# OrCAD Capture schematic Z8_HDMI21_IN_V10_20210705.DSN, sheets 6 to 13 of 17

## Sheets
6 PAGE08-HDMI20 OUT2: size Custom
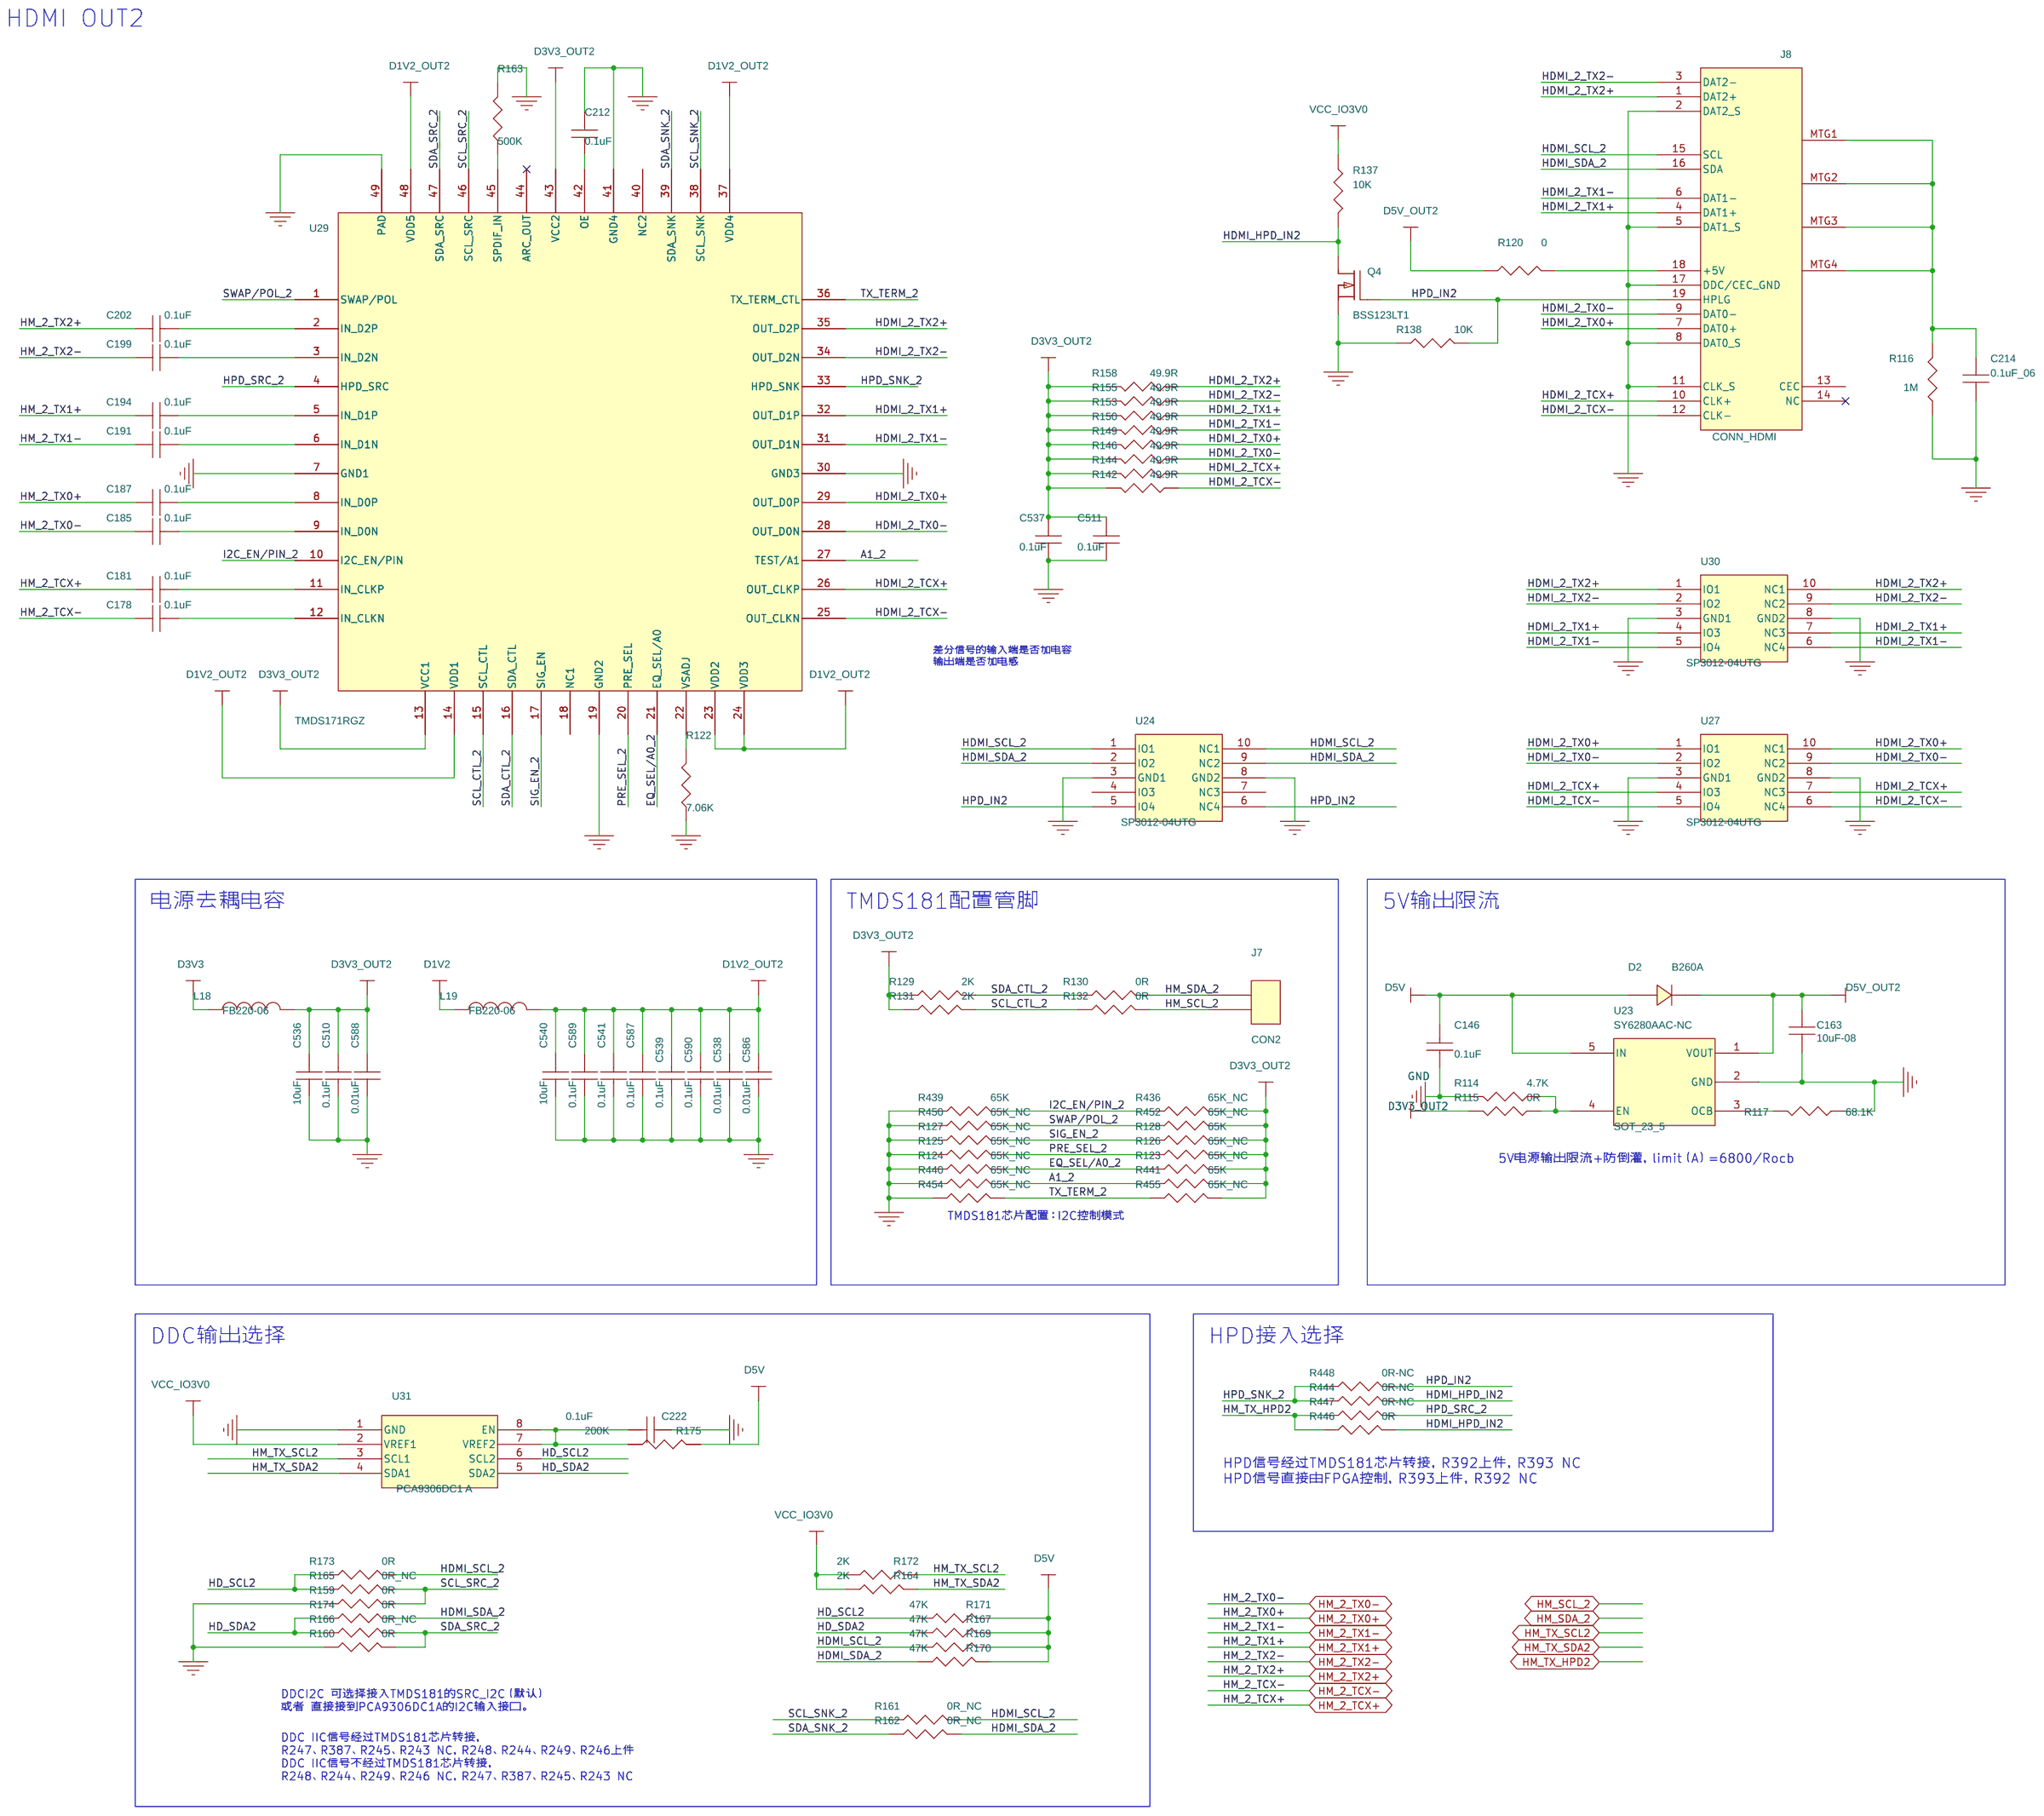
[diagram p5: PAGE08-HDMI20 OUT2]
7 PAGE07-HDMI20 OUT1: size Custom
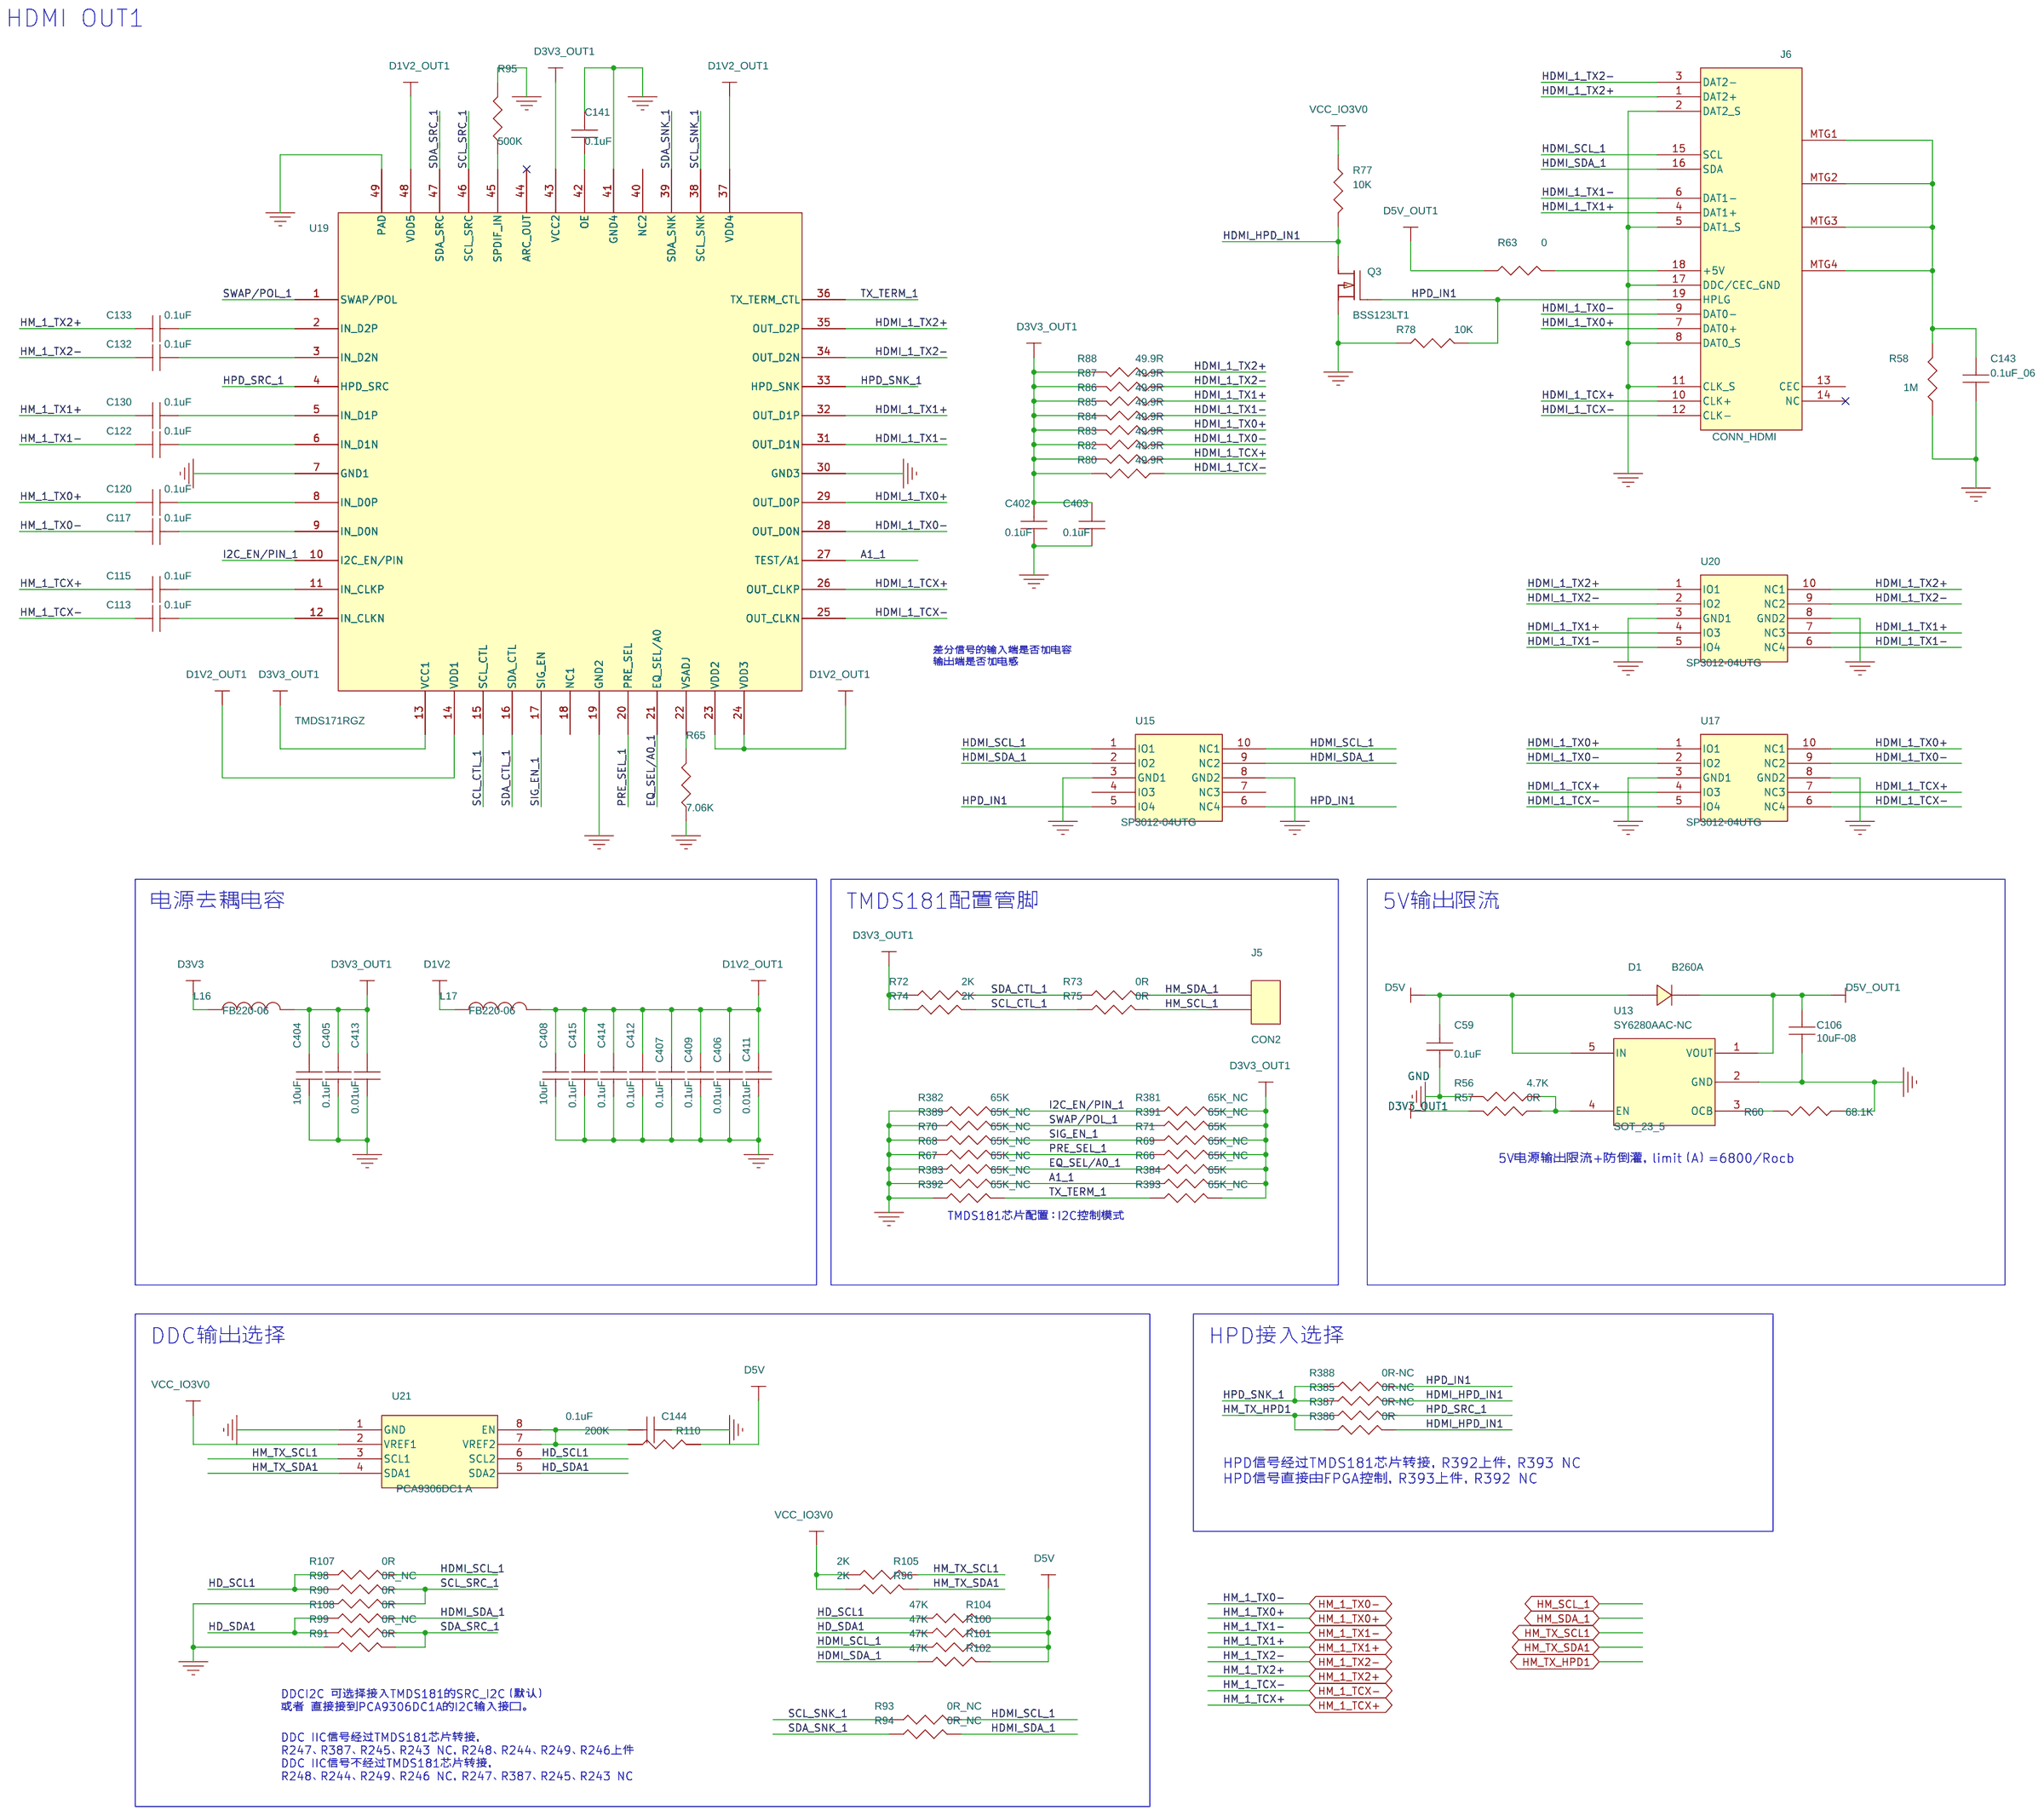
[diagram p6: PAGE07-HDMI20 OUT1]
8 PAGE05-STM32F030: size B
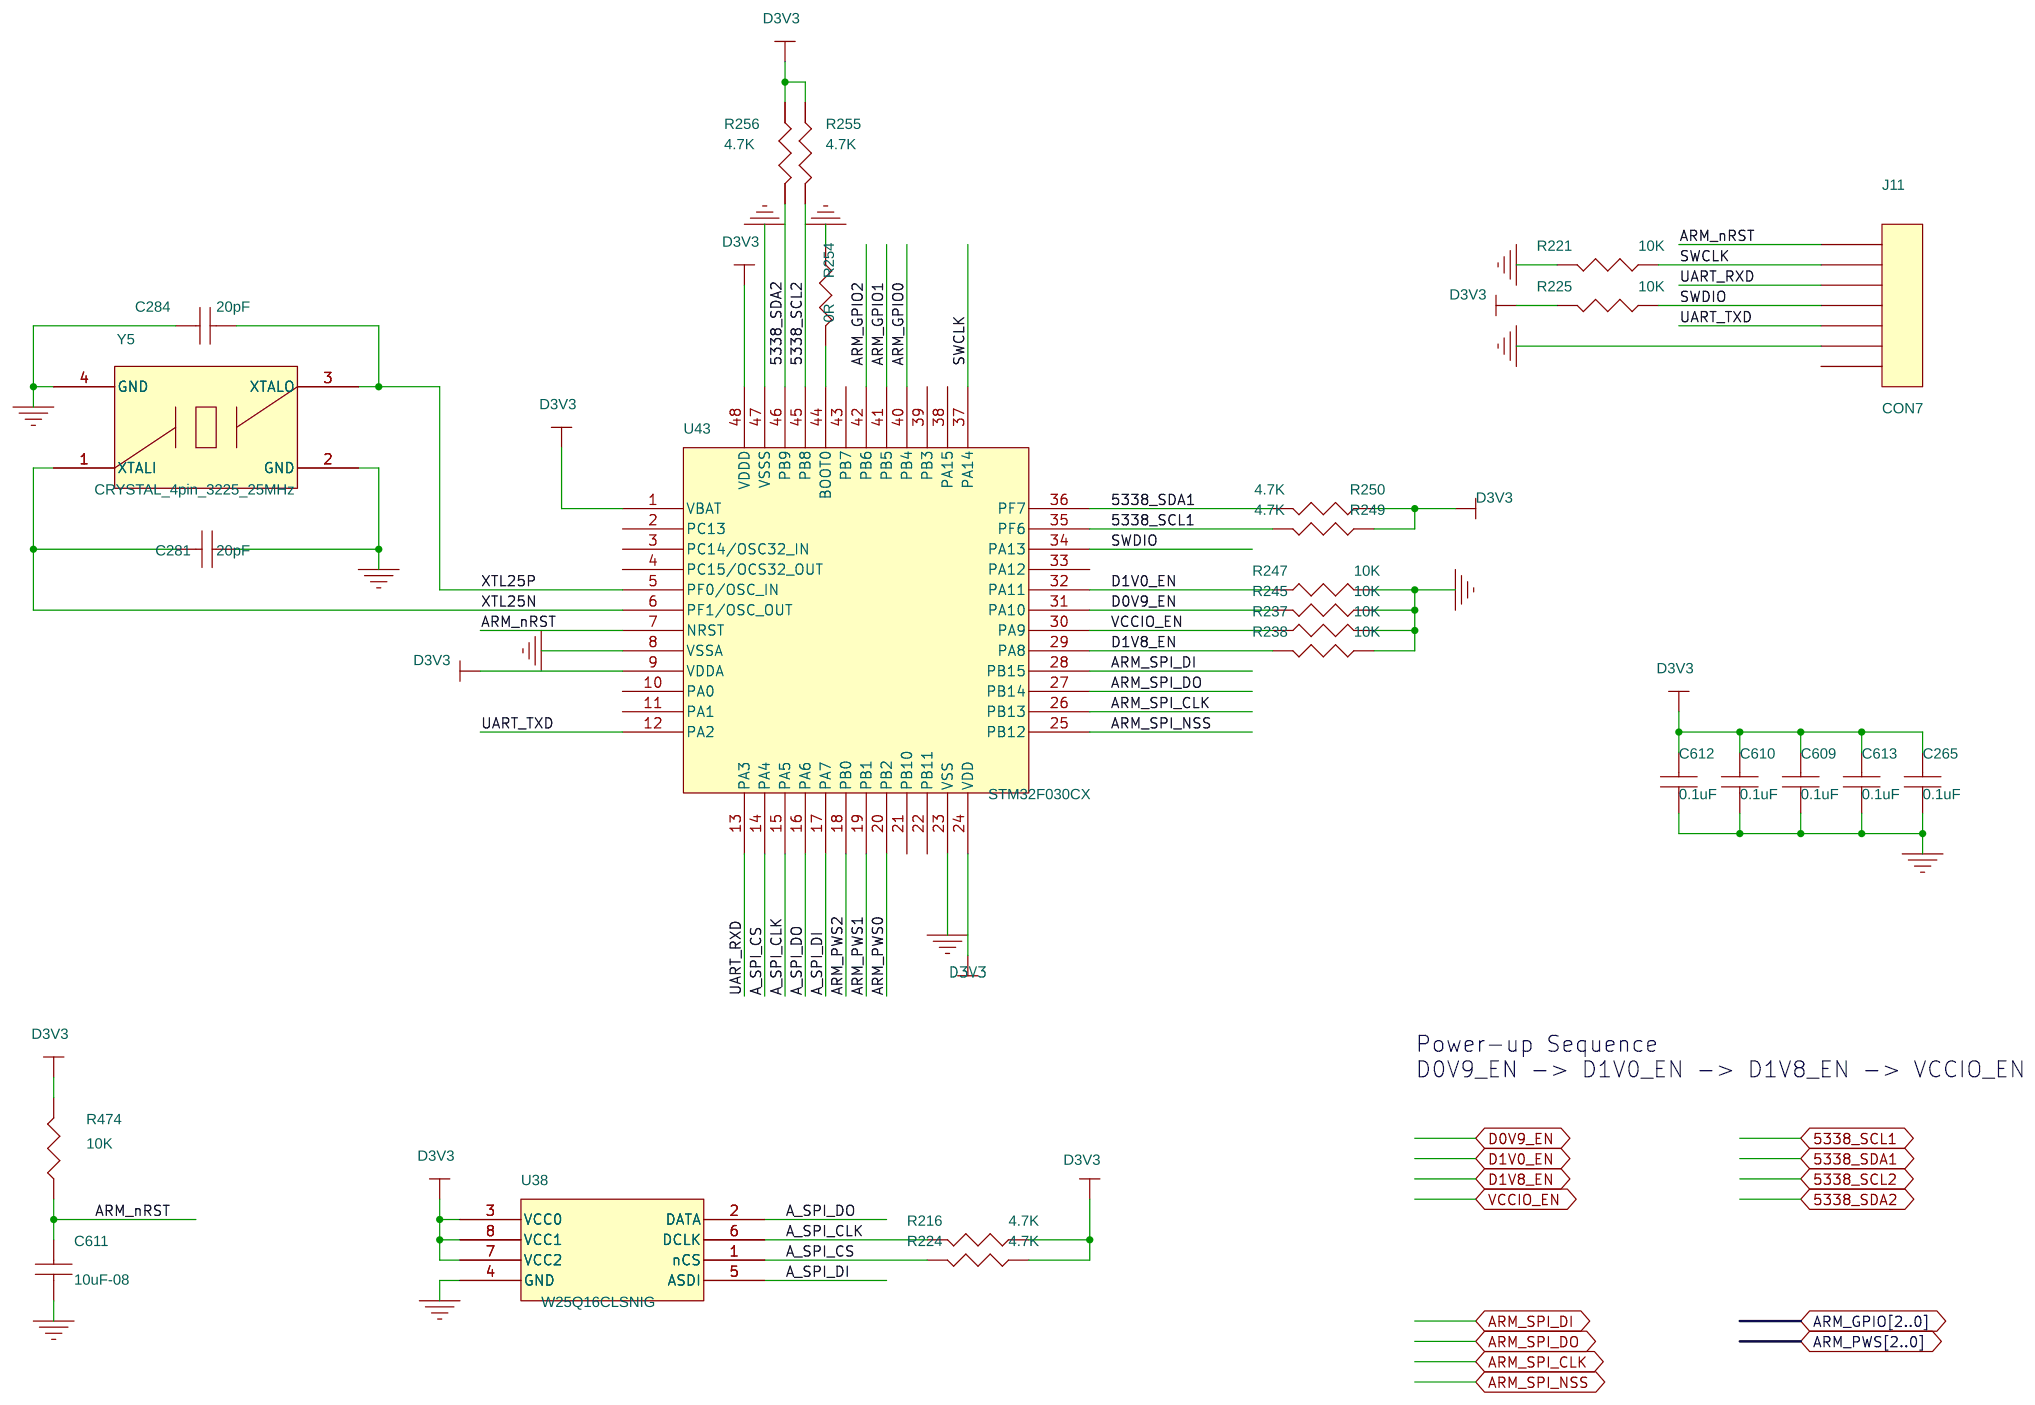
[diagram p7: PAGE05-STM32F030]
9 PAGE01-Description
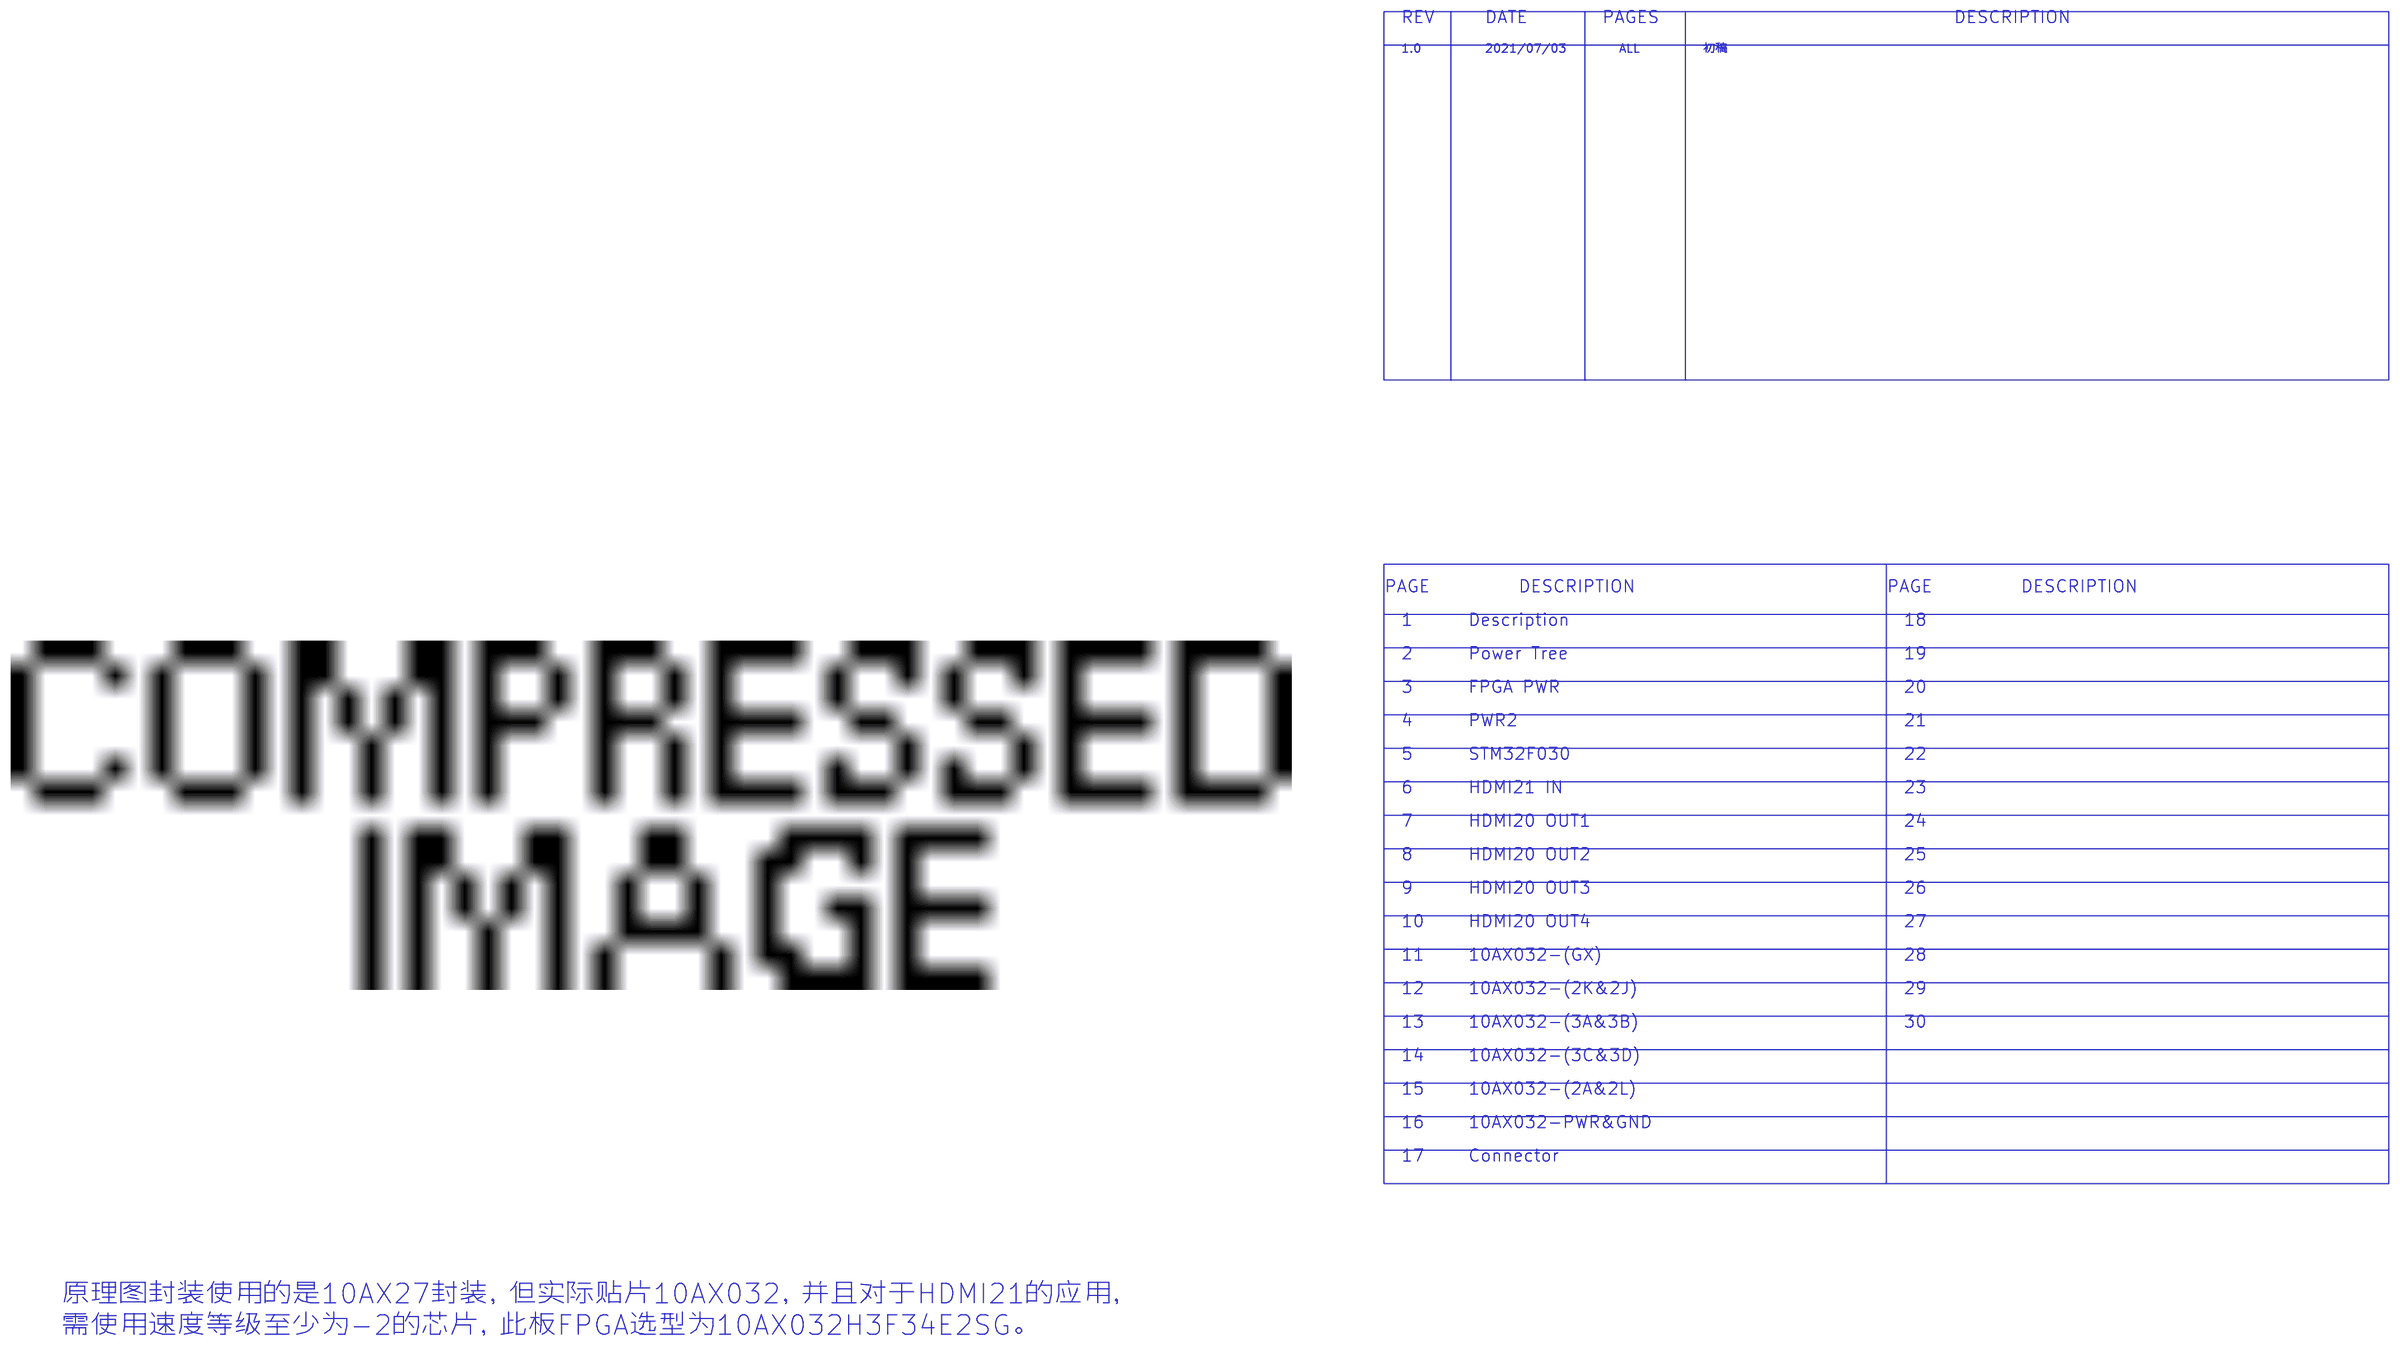
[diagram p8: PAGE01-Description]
10 PAGE04-PWR2: size Custom
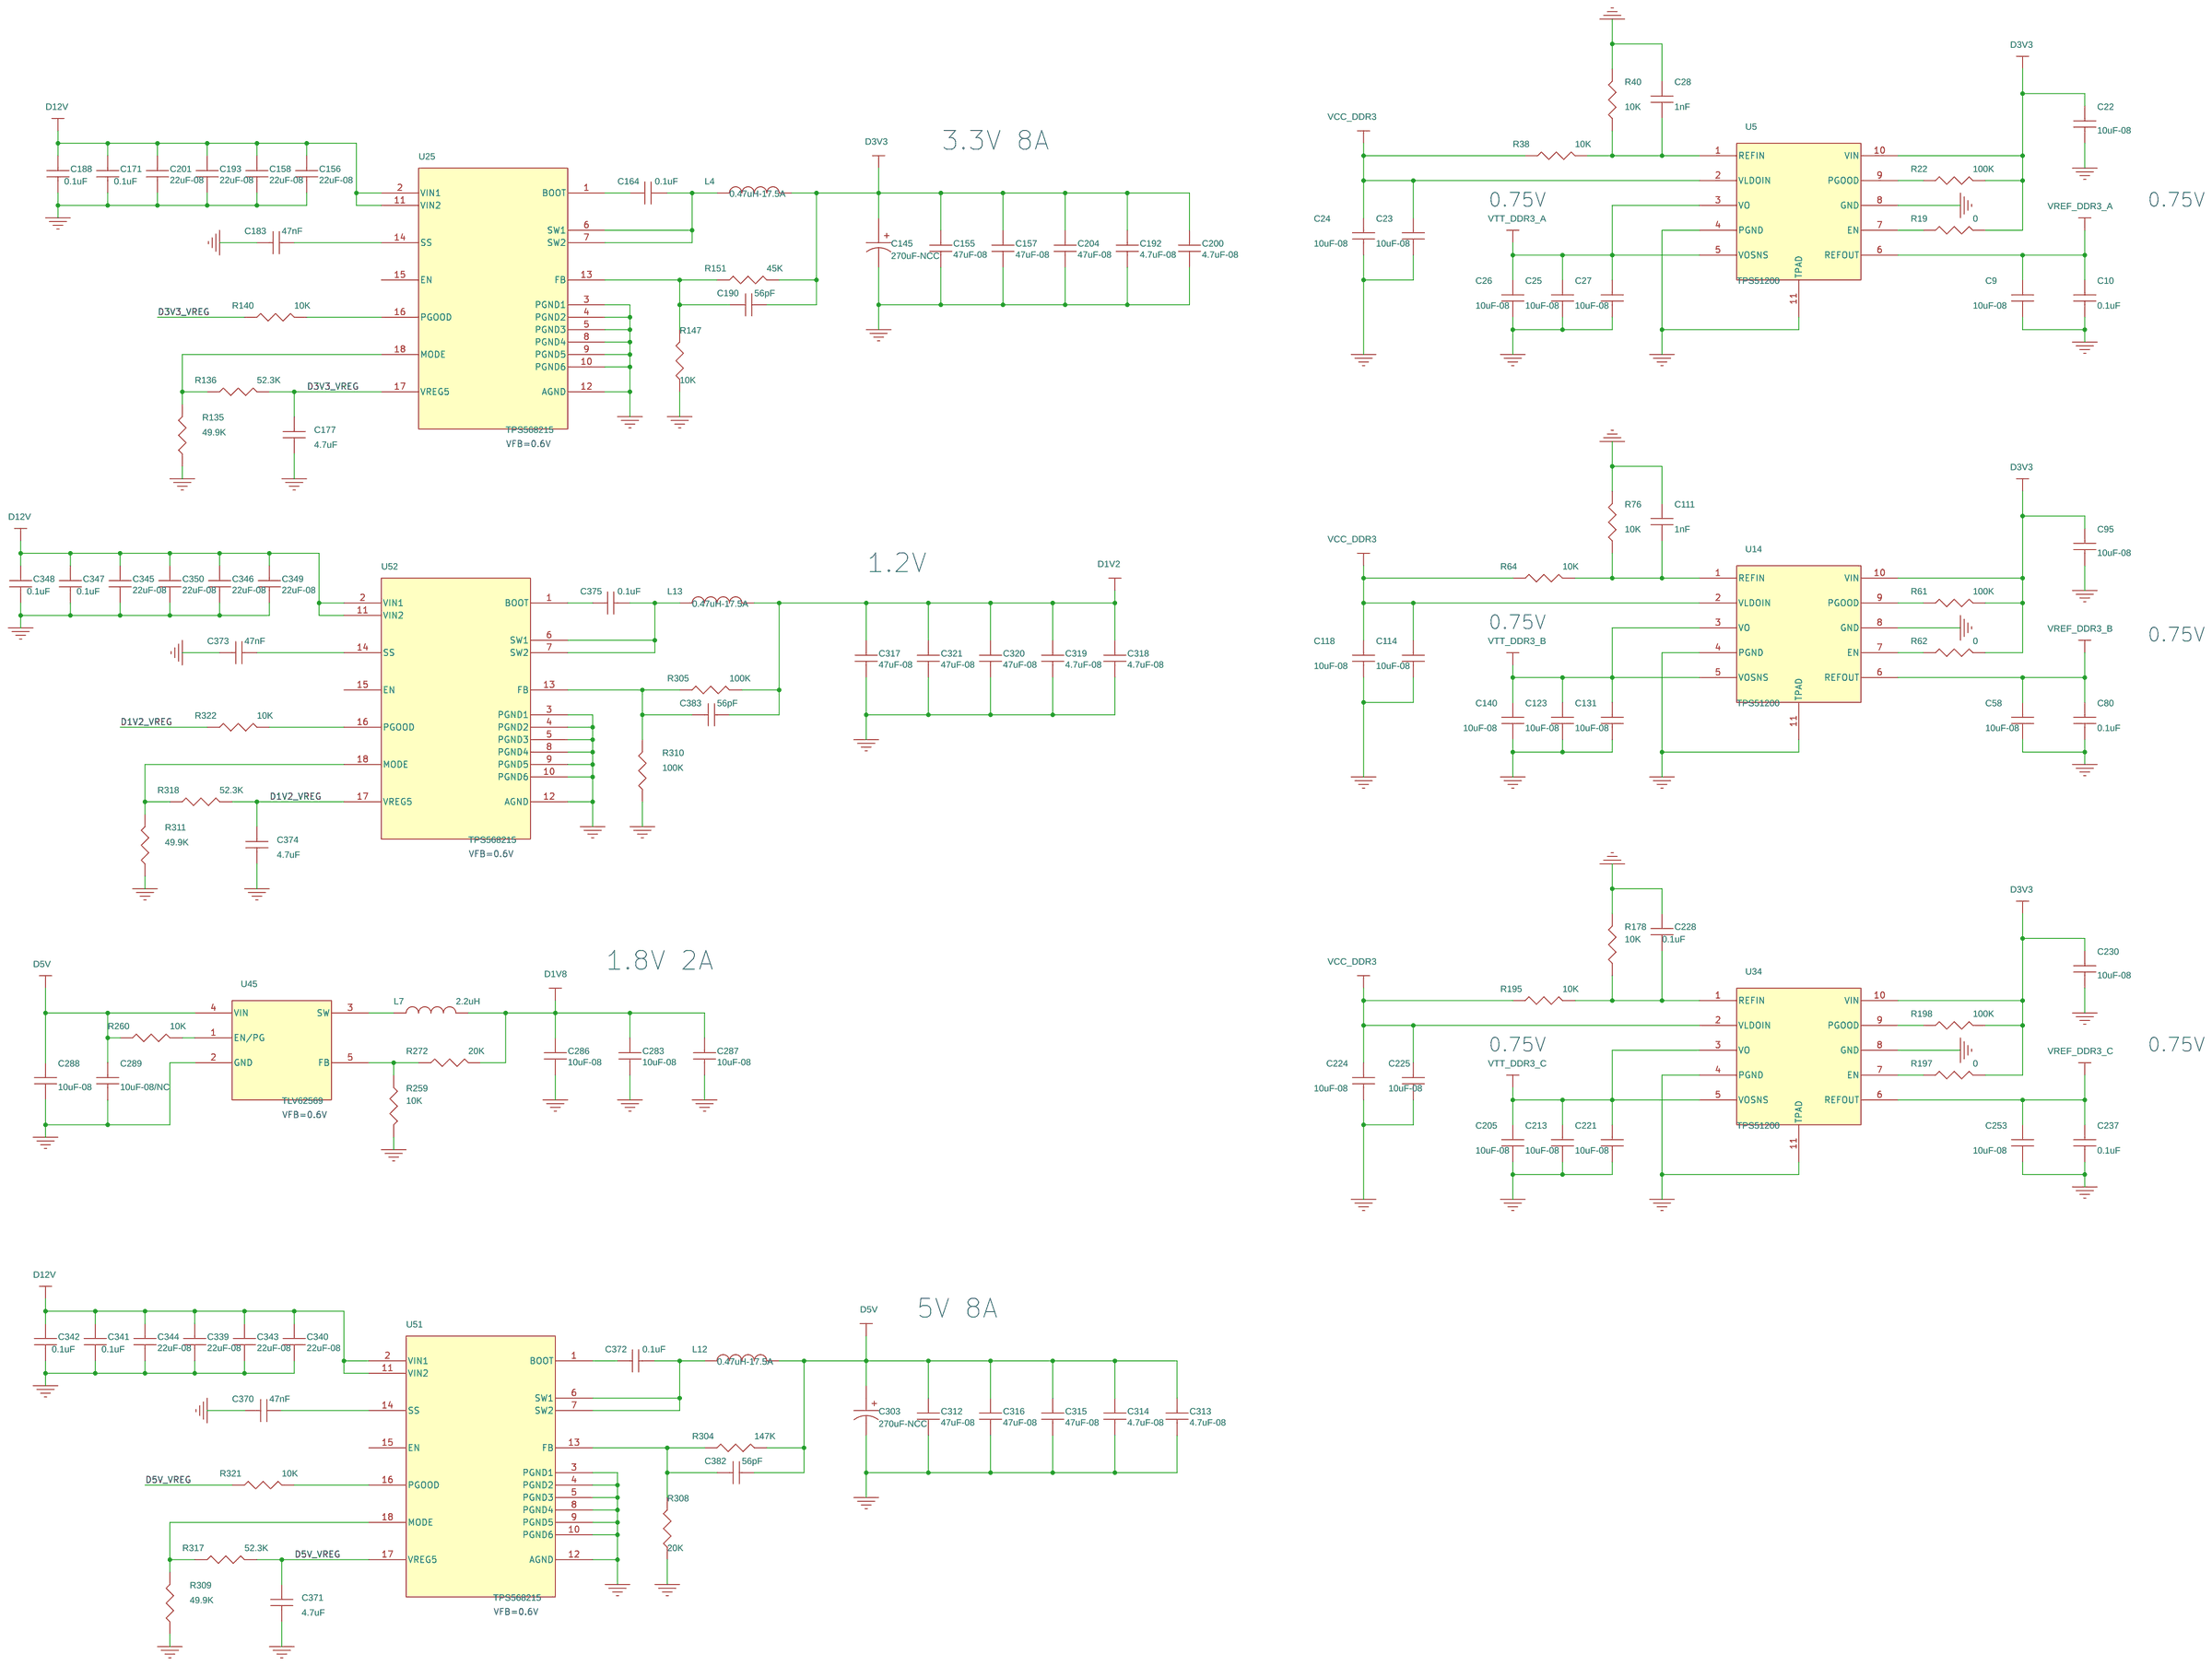
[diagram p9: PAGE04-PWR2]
11 PAGE02-Power Tree
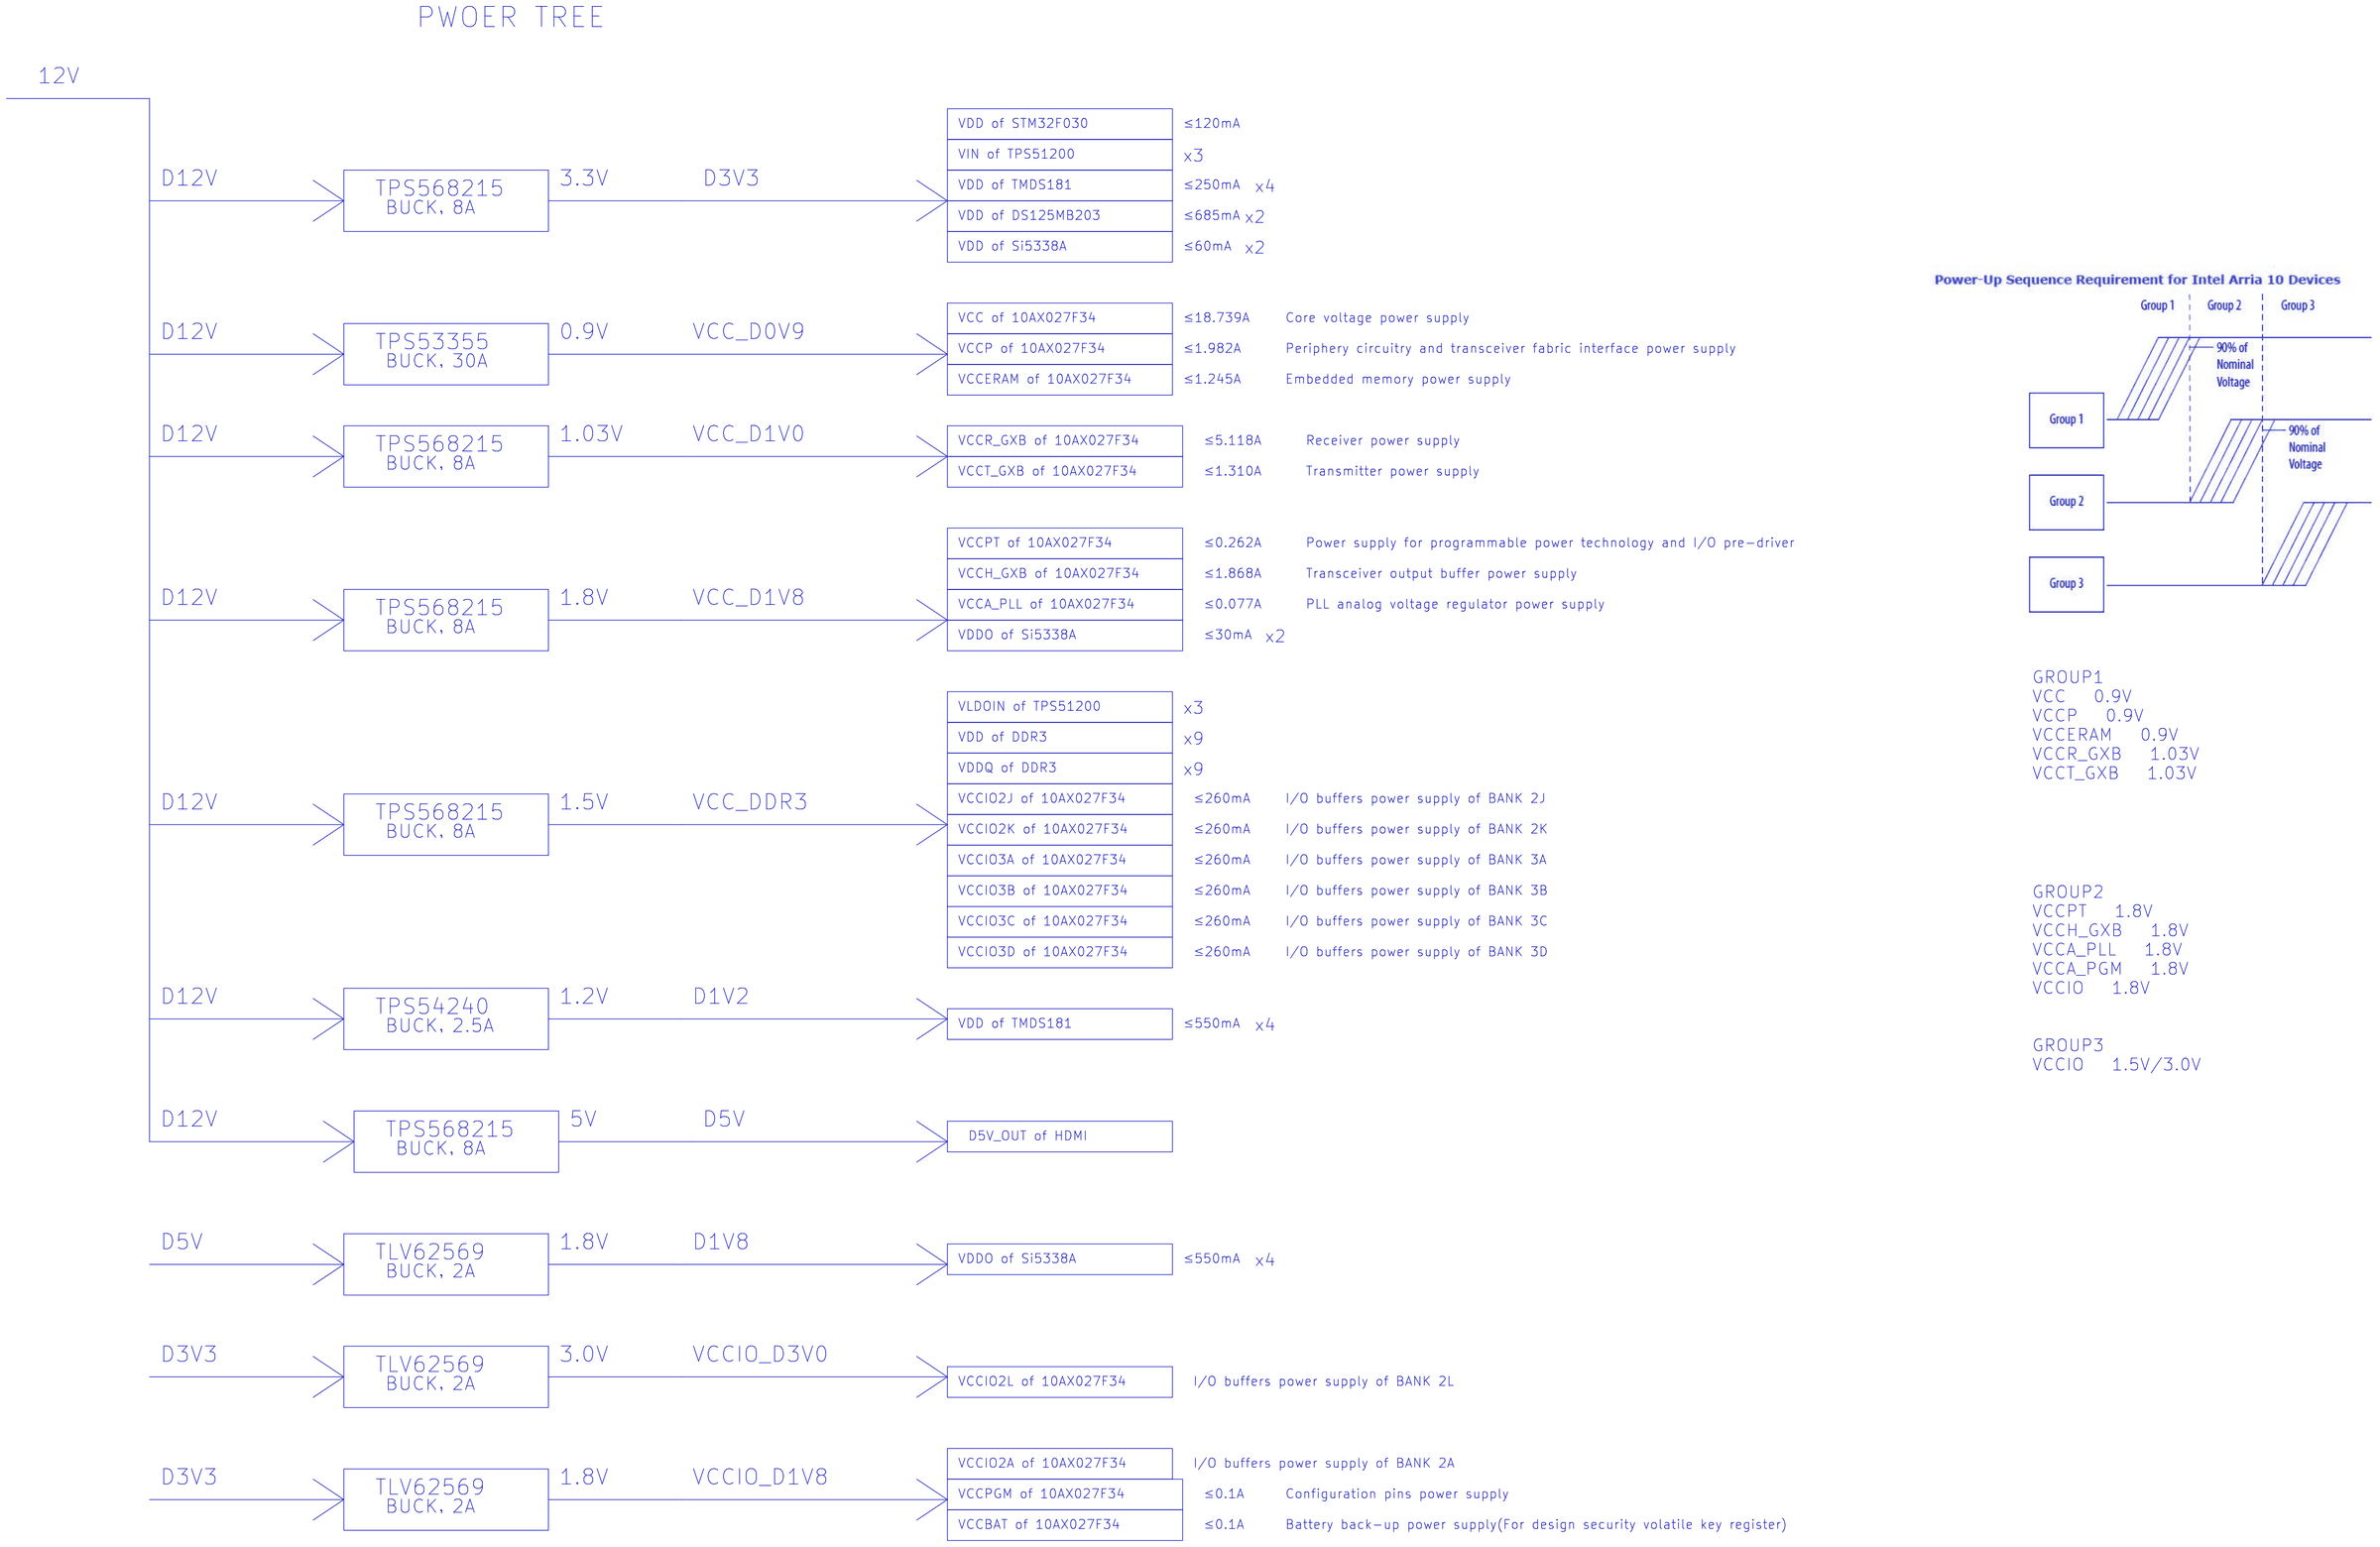
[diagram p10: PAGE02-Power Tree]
12 PAGE17-Connector: size A
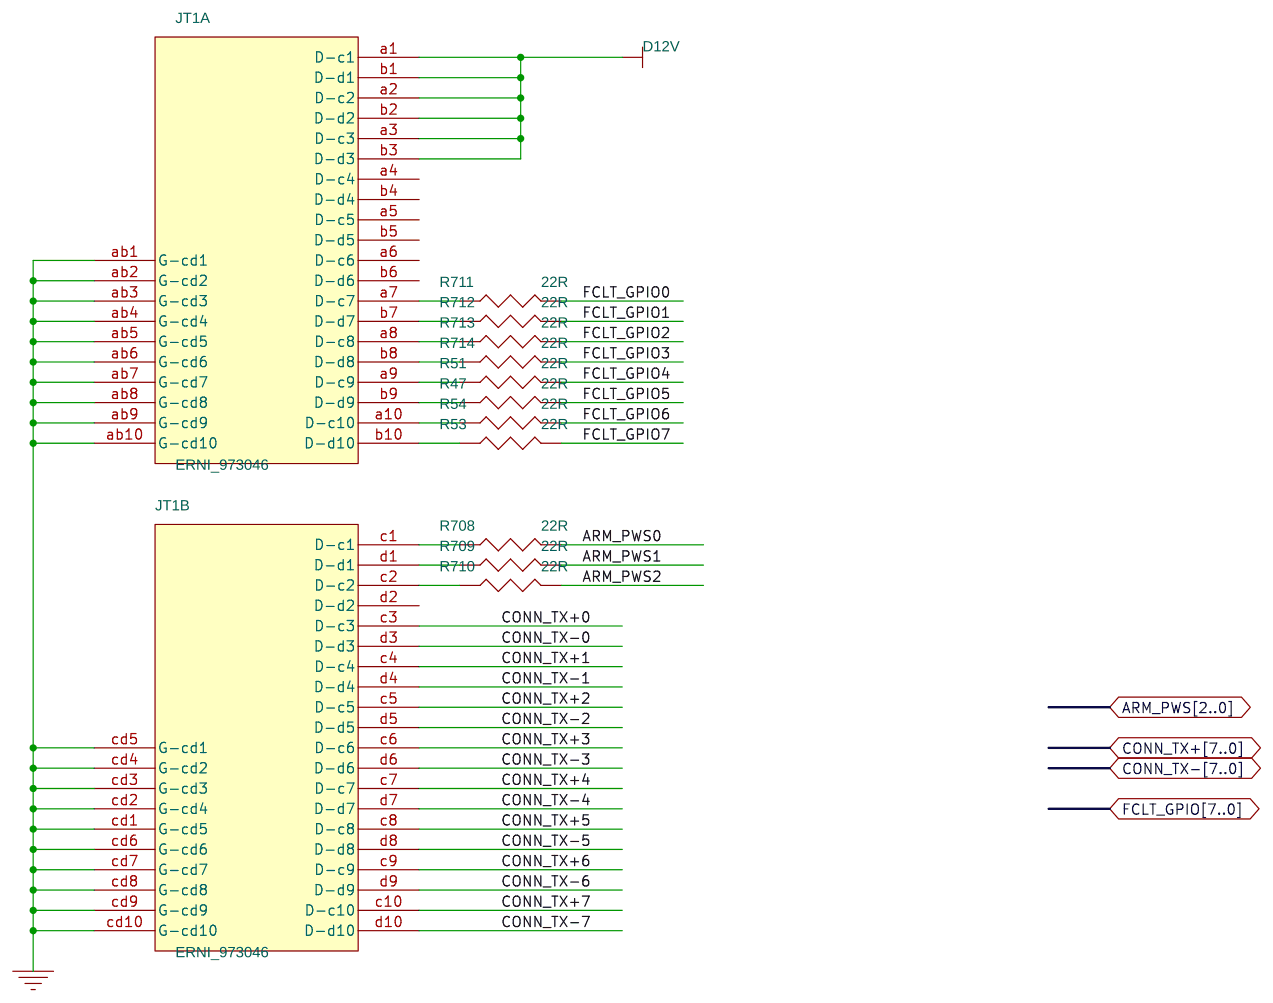
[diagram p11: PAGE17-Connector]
13 PAGE15-10AX032-(2A&2L): size C
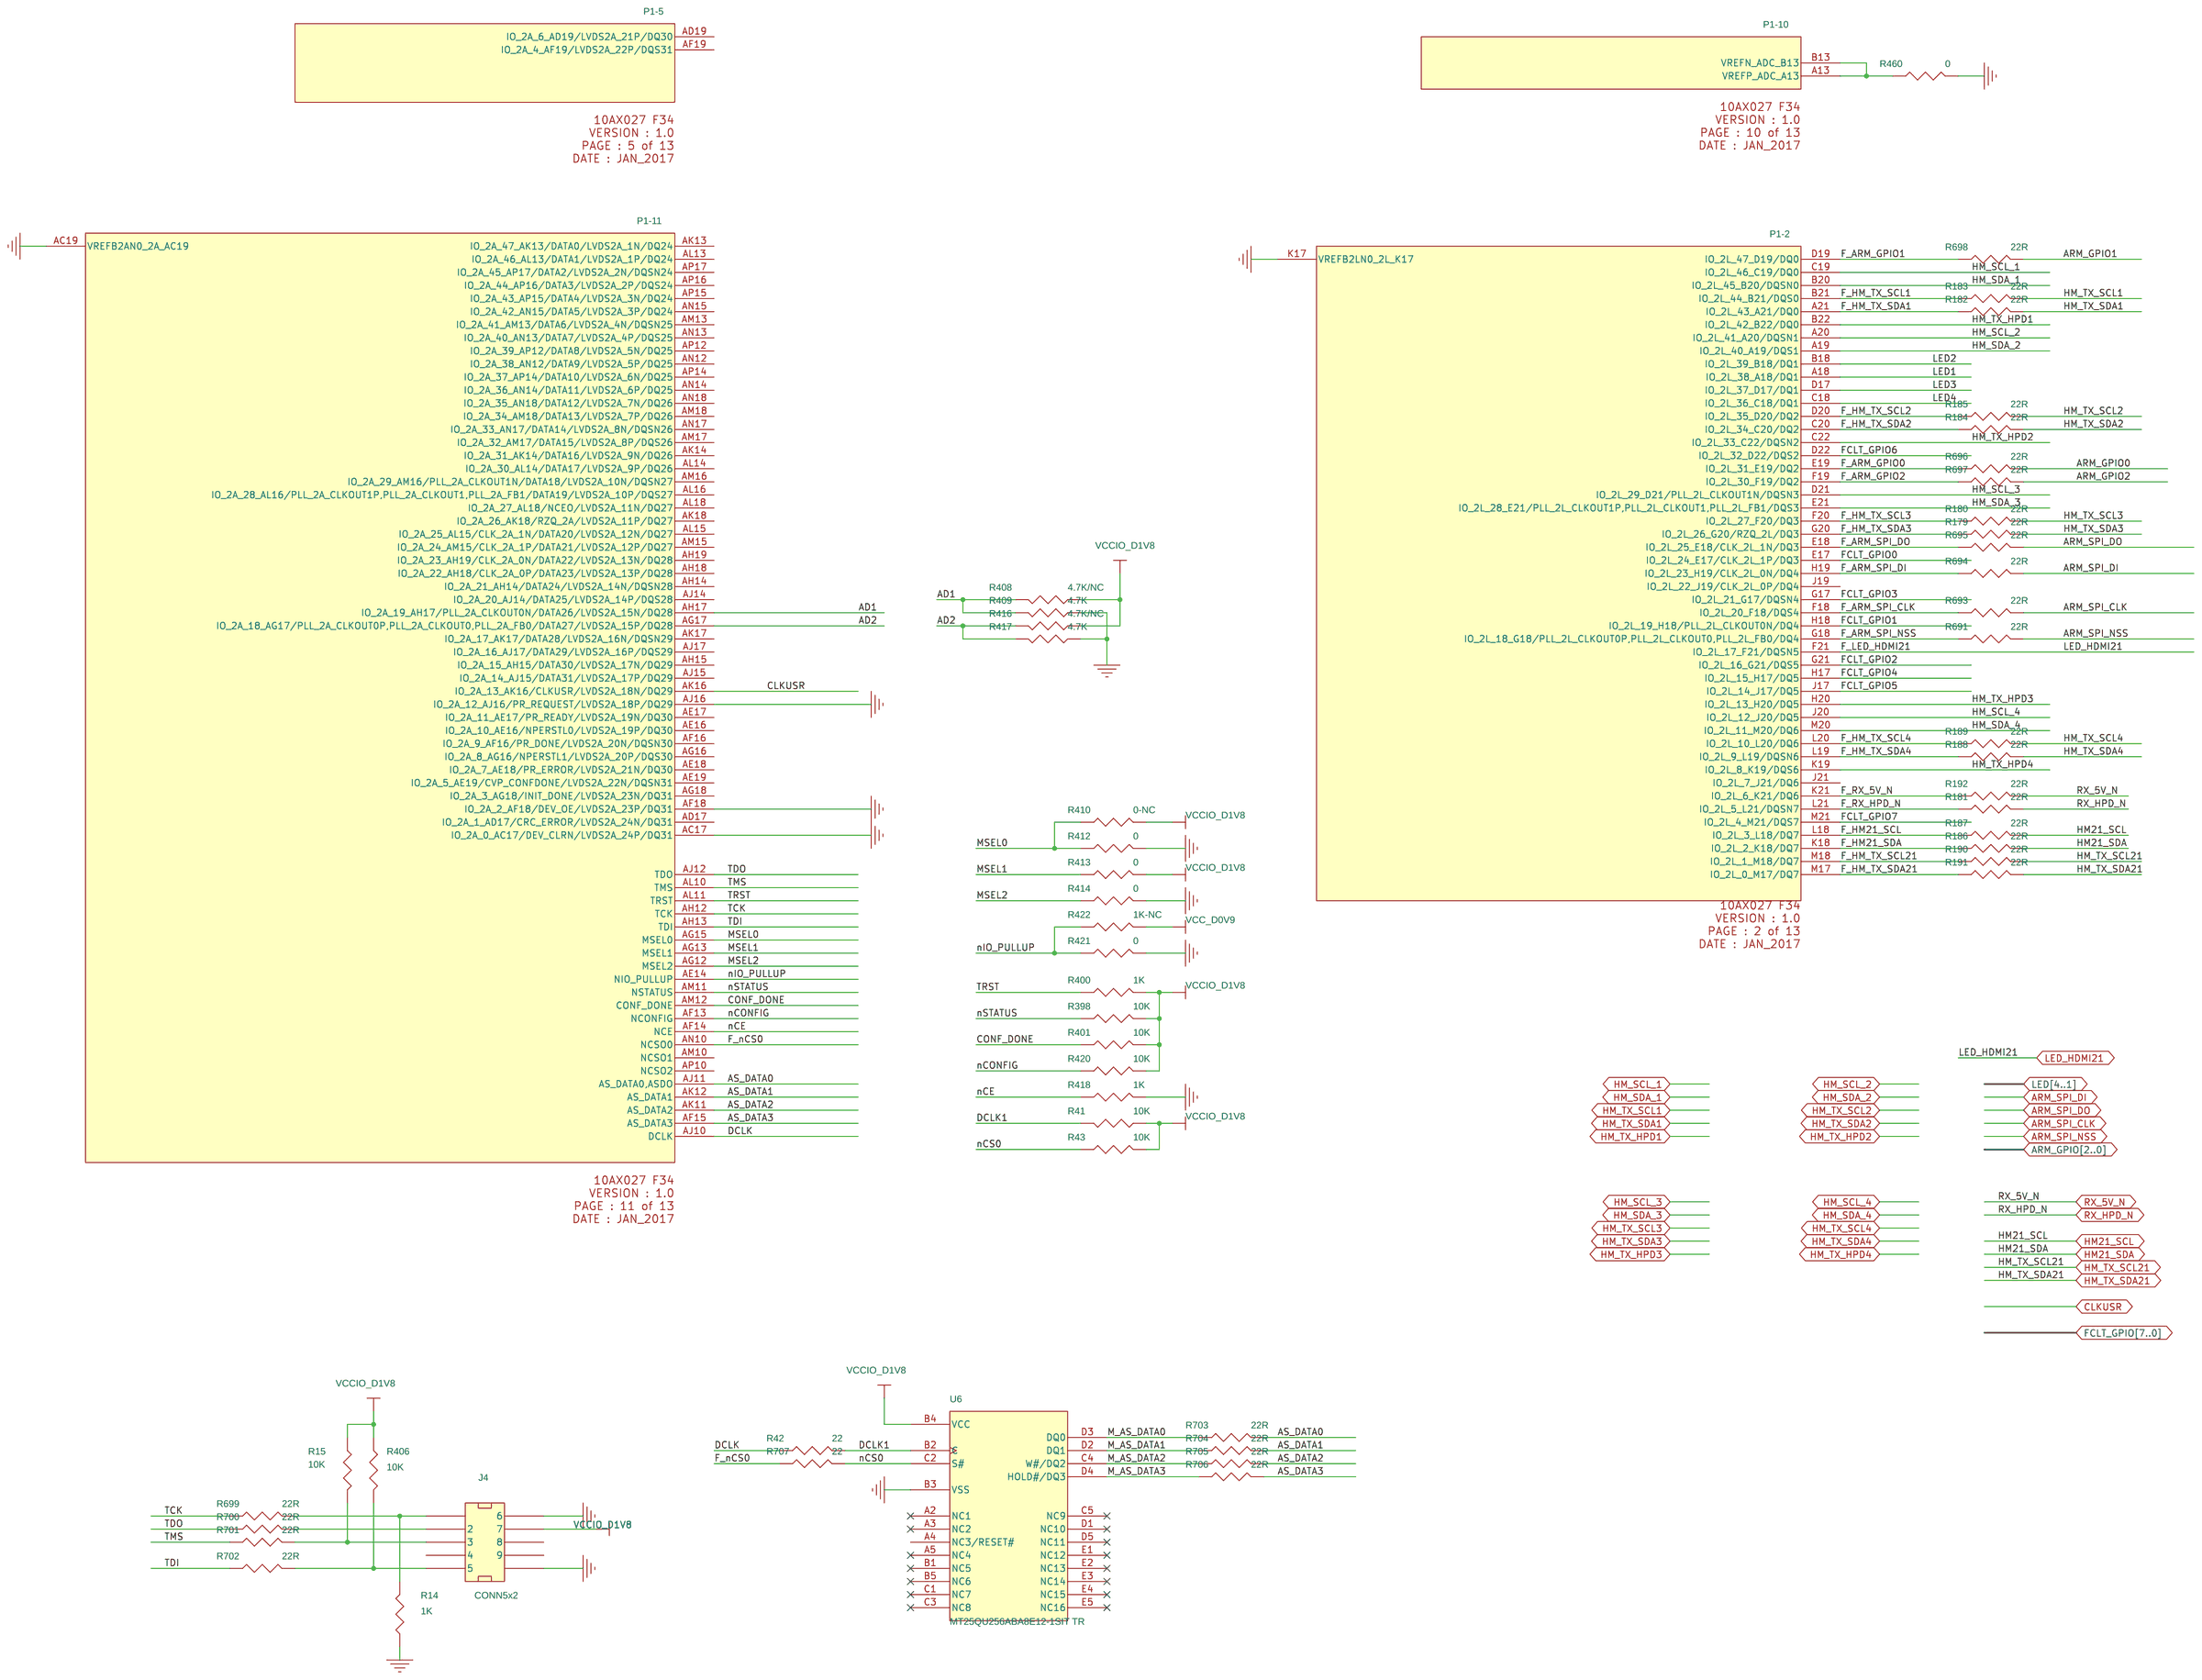
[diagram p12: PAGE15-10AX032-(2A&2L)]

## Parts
sheet PAGE04-PWR2
C9  10uF-08  [C0805]
C10  0.1uF  [C0402]
C22  10uF-08  [C0805]
C23  10uF-08  [C0805]
C24  10uF-08  [C0805]
C25  10uF-08  [C0805]
C26  10uF-08  [C0805]
C27  10uF-08  [C0805]
C28  1nF  [C0402]
C58  10uF-08  [C0805]
C80  0.1uF  [C0402]
C95  10uF-08  [C0805]
C111  1nF  [C0402]
C114  10uF-08  [C0805]
C118  10uF-08  [C0805]
C123  10uF-08  [C0805]
C131  10uF-08  [C0805]
C140  10uF-08  [C0805]
C145  270uF-NCC  [cap196_pol_3_5mm]
C155  47uF-08  [C0805]
C156  22uF-08  [C0805]
C157  47uF-08  [C0805]
C158  22uF-08  [C0805]
C164  0.1uF  [C0402]
C171  0.1uF  [C0402]
C177  4.7uF  [C0402]
C183  47nF  [C0402]
C188  0.1uF  [C0402]
C190  56pF  [C0402]
C192  4.7uF-08  [C0603]
C193  22uF-08  [C0805]
C200  4.7uF-08  [C0603]
C201  22uF-08  [C0805]
C204  47uF-08  [C0805]
C205  10uF-08  [C0805]
C213  10uF-08  [C0805]
C221  10uF-08  [C0805]
C224  10uF-08  [C0805]
C225  10uF-08  [C0805]
C228  0.1uF  [C0402]
C230  10uF-08  [C0805]
C237  0.1uF  [C0402]
C253  10uF-08  [C0805]
C283  10uF-08  [C0805]
C286  10uF-08  [C0805]
C287  10uF-08  [C0805]
C288  10uF-08  [C0805]
C289  10uF-08/NC  [C0805]
C303  270uF-NCC  [cap196_pol_3_5mm]
C312  47uF-08  [C0805]
C313  4.7uF-08  [C0603]
C314  4.7uF-08  [C0603]
C315  47uF-08  [C0805]
C316  47uF-08  [C0805]
C317  47uF-08  [C0805]
C318  4.7uF-08  [C0603]
C319  4.7uF-08  [C0603]
C320  47uF-08  [C0805]
C321  47uF-08  [C0805]
C339  22uF-08  [C0805]
C340  22uF-08  [C0805]
C341  0.1uF  [C0402]
C342  0.1uF  [C0402]
C343  22uF-08  [C0805]
C344  22uF-08  [C0805]
C345  22uF-08  [C0805]
C346  22uF-08  [C0805]
C347  0.1uF  [C0402]
C348  0.1uF  [C0402]
C349  22uF-08  [C0805]
C350  22uF-08  [C0805]
C370  47nF  [C0402]
C371  4.7uF  [C0402]
C372  0.1uF  [C0402]
C373  47nF  [C0402]
C374  4.7uF  [C0402]
C375  0.1uF  [C0402]
C382  56pF  [C0402]
C383  56pF  [C0402]
L4  0.47uH-17.5A  [l_gfb_58x28]
L7  2.2uH  [IND4X4]
L12  0.47uH-17.5A  [l_gfb_58x28]
L13  0.47uH-17.5A  [l_gfb_58x28]
R19  0  [R0402]
R22  100K  [R0402]
R38  10K  [R0402]
R40  10K  [R0402]
R61  100K  [R0402]
R62  0  [R0402]
R64  10K  [R0402]
R76  10K  [R0402]
R135  49.9K  [R0402]
R136  52.3K  [R0402]
R140  10K  [R0402]
R147  10K  [R0402]
R151  45K  [R0402]
R178  10K  [R0402]
R195  10K  [R0402]
R197  0  [R0402]
R198  100K  [R0402]
R259  10K  [R0402]
R260  10K  [R0402]
R272  20K  [R0402]
R304  147K  [R0402]
R305  100K  [R0402]
R308  20K  [R0402]
R309  49.9K  [R0402]
R310  100K  [R0402]
R311  49.9K  [R0402]
R317  52.3K  [R0402]
R318  52.3K  [R0402]
R321  10K  [R0402]
R322  10K  [R0402]
U5  TPS51200  [TPS51200]
U14  TPS51200  [TPS51200]
U25  TPS568215  [TPS568215]
U34  TPS51200  [TPS51200]
U45  TLV62569  [sot23-5]
U51  TPS568215  [TPS568215]
U52  TPS568215  [TPS568215]
sheet PAGE05-STM32F030
C265  0.1uF  [C0402]
C281  20pF  [C0402]
C284  20pF  [C0402]
C609  0.1uF  [C0402]
C610  0.1uF  [C0402]
C611  10uF-08  [C0805]
C612  0.1uF  [C0402]
C613  0.1uF  [C0402]
J11  CON7  [CONN7]
R216  4.7K  [R0402]
R221  10K  [R0402]
R224  4.7K  [R0402]
R225  10K  [R0402]
R237  10K  [R0402]
R238  10K  [R0402]
R245  10K  [R0402]
R247  10K  [R0402]
R249  4.7K  [R0402]
R250  4.7K  [R0402]
R254  0R  [R0402]
R255  4.7K  [R0402]
R256  4.7K  [R0402]
R474  10K  [R0402]
U38  W25Q16CLSNIG  [SOIC8W]
U43  STM32F030CX  [LQFP48]
Y5  CRYSTAL_4pin_3225_25MHz  [XTAL_ABM8]
sheet PAGE07-HDMI20 OUT1
C59  0.1uF  [C0402]
C106  10uF-08  [C0805]
C113  0.1uF  [C0402]
C115  0.1uF  [C0402]
C117  0.1uF  [C0402]
C120  0.1uF  [C0402]
C122  0.1uF  [C0402]
C130  0.1uF  [C0402]
C132  0.1uF  [C0402]
C133  0.1uF  [C0402]
C141  0.1uF  [C0402]
C143  0.1uF_06  [C0402]
C144  0.1uF  [C0402]
C402  0.1uF  [C0402]
C403  0.1uF  [C0402]
C404  10uF  [C0402]
C405  0.1uF  [C0402]
C406  0.01uF  [C0402]
C407  0.1uF  [C0402]
C408  10uF  [C0402]
C409  0.1uF  [C0402]
C411  0.01uF  [C0402]
C412  0.1uF  [C0402]
C413  0.01uF  [C0402]
C414  0.1uF  [C0402]
C415  0.1uF  [C0402]
D1  B260A  [SMA_DIODES]
J5  CON2  [CON2]
J6  CONN_HDMI  [hdmi]
L16  FB220-06  [my_0603_res]
L17  FB220-06  [my_0603_res]
Q3  BSS123LT1  [SOT-23]
R56  4.7K  [R0402]
R57  0R  [R0402]
R58  1M  [R0402]
R60  68.1K  [R0402]
R63  0  [R0402]
R65  7.06K  [R0402]
R66  65K_NC  [R0402]
R67  65K_NC  [R0402]
R68  65K_NC  [R0402]
R69  65K_NC  [R0402]
R70  65K_NC  [R0402]
R71  65K  [R0402]
R72  2K  [R0402]
R73  0R  [R0402]
R74  2K  [R0402]
R75  0R  [R0402]
R77  10K  [R0402]
R78  10K  [R0402]
R80  49.9R  [R0402]
R82  49.9R  [R0402]
R83  49.9R  [R0402]
R84  49.9R  [R0402]
R85  49.9R  [R0402]
R86  49.9R  [R0402]
R87  49.9R  [R0402]
R88  49.9R  [R0402]
R90  0R  [R0402]
R91  0R  [R0402]
R93  0R_NC  [R0402]
R94  0R_NC  [R0402]
R95  500K  [R0402]
R96  2K  [R0402]
R98  0R_NC  [R0402]
R99  0R_NC  [R0402]
R100  47K  [R0402]
R101  47K  [R0402]
R102  47K  [R0402]
R104  47K  [R0402]
R105  2K  [R0402]
R107  0R  [R0402]
R108  0R  [R0402]
R110  200K  [R0402]
R381  65K_NC  [R0402]
R382  65K  [R0402]
R383  65K_NC  [R0402]
R384  65K  [R0402]
R385  0R-NC  [R0402]
R386  0R  [R0402]
R387  0R-NC  [R0402]
R388  0R-NC  [R0402]
R389  65K_NC  [R0402]
R391  65K_NC  [R0402]
R392  65K_NC  [R0402]
R393  65K_NC  [R0402]
U13  SY6280AAC-NC  [SOT_23_5]
U15  SP3012-04UTG  [uDFN-10]
U17  SP3012-04UTG  [uDFN-10]
U19  TMDS171RGZ  [QFN48_TMDS181]
U20  SP3012-04UTG  [uDFN-10]
U21  PCA9306DC1 A  [SOIC8_E0D65_4D55XE3D15]
sheet PAGE08-HDMI20 OUT2
C146  0.1uF  [C0402]
C163  10uF-08  [C0805]
C178  0.1uF  [C0402]
C181  0.1uF  [C0402]
C185  0.1uF  [C0402]
C187  0.1uF  [C0402]
C191  0.1uF  [C0402]
C194  0.1uF  [C0402]
C199  0.1uF  [C0402]
C202  0.1uF  [C0402]
C212  0.1uF  [C0402]
C214  0.1uF_06  [C0402]
C222  0.1uF  [C0402]
C510  0.1uF  [C0402]
C511  0.1uF  [C0402]
C536  10uF  [C0402]
C537  0.1uF  [C0402]
C538  0.01uF  [C0402]
C539  0.1uF  [C0402]
C540  10uF  [C0402]
C541  0.1uF  [C0402]
C586  0.01uF  [C0402]
C587  0.1uF  [C0402]
C588  0.01uF  [C0402]
C589  0.1uF  [C0402]
C590  0.1uF  [C0402]
D2  B260A  [SMA_DIODES]
J7  CON2  [CON2]
J8  CONN_HDMI  [hdmi]
L18  FB220-06  [my_0603_res]
L19  FB220-06  [my_0603_res]
Q4  BSS123LT1  [SOT-23]
R114  4.7K  [R0402]
R115  0R  [R0402]
R116  1M  [R0402]
R117  68.1K  [R0402]
R120  0  [R0402]
R122  7.06K  [R0402]
R123  65K_NC  [R0402]
R124  65K_NC  [R0402]
R125  65K_NC  [R0402]
R126  65K_NC  [R0402]
R127  65K_NC  [R0402]
R128  65K  [R0402]
R129  2K  [R0402]
R130  0R  [R0402]
R131  2K  [R0402]
R132  0R  [R0402]
R137  10K  [R0402]
R138  10K  [R0402]
R142  49.9R  [R0402]
R144  49.9R  [R0402]
R146  49.9R  [R0402]
R149  49.9R  [R0402]
R150  49.9R  [R0402]
R153  49.9R  [R0402]
R155  49.9R  [R0402]
R158  49.9R  [R0402]
R159  0R  [R0402]
R160  0R  [R0402]
R161  0R_NC  [R0402]
R162  0R_NC  [R0402]
R163  500K  [R0402]
R164  2K  [R0402]
R165  0R_NC  [R0402]
R166  0R_NC  [R0402]
R167  47K  [R0402]
R169  47K  [R0402]
R170  47K  [R0402]
R171  47K  [R0402]
R172  2K  [R0402]
R173  0R  [R0402]
R174  0R  [R0402]
R175  200K  [R0402]
R436  65K_NC  [R0402]
R439  65K  [R0402]
R440  65K_NC  [R0402]
R441  65K  [R0402]
R444  0R-NC  [R0402]
R446  0R  [R0402]
R447  0R-NC  [R0402]
R448  0R-NC  [R0402]
R450  65K_NC  [R0402]
R452  65K_NC  [R0402]
R454  65K_NC  [R0402]
R455  65K_NC  [R0402]
U23  SY6280AAC-NC  [SOT_23_5]
U24  SP3012-04UTG  [uDFN-10]
U27  SP3012-04UTG  [uDFN-10]
U29  TMDS171RGZ  [QFN48_TMDS181]
U30  SP3012-04UTG  [uDFN-10]
U31  PCA9306DC1 A  [SOIC8_E0D65_4D55XE3D15]
sheet PAGE12-10AX032-(2K&2J)
P1  10AX027 F34  [BGA1152_PAD18]  (sections -1,-10,-11,-12,-13,-2,-3,-4,-5,-6,-7,-8,-9)
sheet PAGE15-10AX032-(2A&2L)
J4  CONN5x2  [conn10]
R14  1K  [R0402]
R15  10K  [R0402]
R41  10K  [R0402]
R42  22  [R0402]
R43  10K  [R0402]
R179  22R  [C0402-8]
R180  22R  [C0402-8]
R181  22R  [C0402-8]
R182  22R  [C0402-8]
R183  22R  [C0402-8]
R184  22R  [C0402-8]
R185  22R  [C0402-8]
R186  22R  [C0402-8]
R187  22R  [C0402-8]
R188  22R  [C0402-8]
R189  22R  [C0402-8]
R190  22R  [C0402-8]
R191  22R  [C0402-8]
R192  22R  [C0402-8]
R398  10K  [C0402-8]
R400  1K  [R0402]
R401  10K  [C0402-8]
R406  10K  [R0402]
R408  4.7K/NC  [R0402]
R409  4.7K  [R0402]
R410  0-NC  [R0402]
R412  0  [R0402]
R413  0  [C0402-8]
R414  0  [C0402-8]
R416  4.7K/NC  [R0402]
R417  4.7K  [R0402]
R418  1K  [C0402-8]
R420  10K  [C0402-8]
R421  0  [R0402]
R422  1K-NC  [R0402]
R460  0  [C0402-8]
R691  22R  [R0402]
R693  22R  [R0402]
R694  22R  [R0402]
R695  22R  [R0402]
R696  22R  [R0402]
R697  22R  [R0402]
R698  22R  [R0402]
R699  22R  [R0402]
R700  22R  [R0402]
R701  22R  [R0402]
R702  22R  [R0402]
R703  22R  [R0402]
R704  22R  [R0402]
R705  22R  [R0402]
R706  22R  [R0402]
R707  22  [R0402]
U6  MT25QU256ABA8E12-1SIT TR  [t-pbga24-ball]
sheet PAGE17-Connector
JT1  ERNI_973046  [ERNI_973046]  (sections A,B)
R47  22R  [R0402]
R51  22R  [R0402]
R53  22R  [R0402]
R54  22R  [R0402]
R708  22R  [R0402]
R709  22R  [R0402]
R710  22R  [R0402]
R711  22R  [R0402]
R712  22R  [R0402]
R713  22R  [R0402]
R714  22R  [R0402]

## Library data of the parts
C9 C10 C22-C28 C58 C59 C80 C95 C106 C111 C113-C115 C117 C118 C120 C122 C123 C130-C133 C140 C141 C144 C146 C155-C158 C163 C164 C171 C177 C178 C181 C183 C185 C187 C188 C190-C194 C199-C202 C204 C205 C212 C213 C221 C222 C224 C225 C228 C230 C237 C253 C265 C283 C286-C289 C312-C321 C339-C350 C370-C375 C382 C383 C402-C409 C411-C415 C510 C511 C536-C541 C586-C590 C609-C613 = CAP_NP
C145 C303 = CAP_POL
L4 L7 L12 L13 L16-L19 = L_0
R14 R15 R19 R22 R38 R40-R43 R47 R51 R53 R54 R56-R58 R60-R78 R80 R82-R88 R90 R91 R93-R96 R98-R102 R104 R105 R107 R108 R110 R114-R117 R120 R122-R132 R135-R138 R140 R142 R144 R146 R147 R149-R151 R153 R155 R158-R167 R169-R175 R178-R192 R195 R197 R198 R216 R221 R224 R225 R237 R238 R245 R247 R249 R250 R254-R256 R259 R260 R272 R304 R305 R308-R311 R317 R318 R321 R322 R381-R389 R391-R393 R398 R400 R401 R406 R408-R410 R412-R414 R416-R418 R420-R422 R436 R439-R441 R444 R446-R448 R450 R452 R454 R455 R460 R474 R691 R693-R714 = R
U5 U14 U34 = TPS54040_0_v3
U25 U51 U52 = TPS54040_0
U45 = TLV62565_0
C281 C284 = CAP_0402_100pF_COG_50V: CAP,CER,C0G,0402,50V,10%,22PF; MANUFACTURER: VISHAY; ORDER#: VJ0402A220KXAA
J11 = CON7
U38 = EPCS1_4
U43 = STM32F051CX
Y5 = CRYSTAL_4pin_3225
C143 C214 = CAP_NP: ROOM: DVI; VOLTAGE: 25V
D1 D2 = DIODE_0
J5 J7 = CON2
J6 J8 = CONN_HDMI_1
Q3 Q4 = MFE825_0
U13 U23 = SWITCH_SY6280: Low Loss Power Distribution Switch; Created by: JJJ; Manufacturer: Silergy（矽力杰）; Manufacturer PN: SY6280AAC; Option: <option>; Part Type: Switch; Priority: A; RK PN: SY6280AAC
U15 U17 U20 U24 U27 U30 = SP3012-04UTG
U19 U29 = DP159RGZ_0: SILKTEXT: 48 PIN RGZ, HSIO
U21 U31 = PCA9306DC1_A
P1 = 10AX027_F34_2
J4 = CONN_SOCKET_5x2
U6 = EPCQL_0: ICS - 1GBIT, MULTI-IO SERIAL NOR FLASH, 1.8V, TBGA-24 (6X8)MM; Item Num: P01-17829R; Lead Free Status: Yes; Manufacturer: Altera; Manufacturer Part Num: EPCQ1024L; Num Pins: 24; Part Class: ICs
JT1 = ERmetZD-MV-973080_1

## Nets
D0V9_EN: R245.2 U43.31(PA10) ; also on sheet 17
D1V0_EN: R247.2 U43.32(PA11) ; also on sheet 17
D1V2: C317.1 C318.1 C319.1 C320.1 C321.1 C383.1 L13.2 L17.2 L19.2 R305.2 ; also on sheet 2 3
D1V2_OUT1: C406.2 C407.2 C408.2 C409.2 C411.2 C412.2 C414.2 C415.2 L17.1 U19.14(VDD1) U19.23(VDD2) U19.24(VDD3) U19.37(VDD4) U19.48(VDD5)
D1V2_OUT2: C538.2 C539.2 C540.2 C541.2 C586.2 C587.2 C589.2 C590.2 L19.1 U29.14(VDD1) U29.23(VDD2) U29.24(VDD3) U29.37(VDD4) U29.48(VDD5)
D1V2_VREG: C374.1 R318.2 R322.1 U52.17(VREG5)
D1V8: C283.1 C286.1 C287.1 L7.2 R272.2 ; also on sheet 5
D1V8_EN: R238.2 U43.29(PA8) ; also on sheet 17
D3V3: C22.1 C95.1 C145.1 C155.1 C157.1 C190.1 C192.1 C200.1 C204.1 C230.1 C265.1 C609.1 C610.1 C612.1 C613.1 L4.2 L16.2 L18.2 R19.2 R22.2 R61.2 R62.2 R151.2 R197.2 R198.2 R216.2 R224.2 R225.1 R249.2 R250.2 R255.2 R256.2 R474.1 U5.10(VIN) U14.10(VIN) U34.10(VIN) U38.3(VCC0) U38.7(VCC2) U38.8(VCC1) U43.1(VBAT) U43.9(VDDA) U43.24(VDD) U43.48(VDDD) ; also on sheet 1 2 3 5 17
D3V3_OUT1: C402.2 C403.2 C404.2 C405.2 C413.2 L16.1 R57.2 R66.1 R69.1 R71.1 R72.1 R74.1 R80.1 R82.1 R83.1 R84.1 R85.1 R86.1 R87.1 R88.1 R381.1 R384.1 R391.1 R393.1 U19.13(VCC1) U19.43(VCC2)
D3V3_OUT2: C510.2 C511.2 C536.2 C537.2 C588.2 L18.1 R115.2 R123.1 R126.1 R128.1 R129.1 R131.1 R142.1 R144.1 R146.1 R149.1 R150.1 R153.1 R155.1 R158.1 R436.1 R441.1 R452.1 R455.1 U29.13(VCC1) U29.43(VCC2)
D3V3_VREG: C177.1 R136.2 R140.1 U25.17(VREG5)
D5V: C59.2 C146.2 C288.1 C289.1 C303.1 C312.1 C313.1 C314.1 C315.1 C316.1 C382.1 D1.2(A) D2.2(A) L12.2 R100.2 R101.2 R102.2 R104.2 R110.2 R167.2 R169.2 R170.2 R171.2 R175.2 R260.1 R304.2 U13.5(IN) U23.5(IN) U45.4(VIN) ; also on sheet 1 2 3
D5V_OUT1: C106.1 D1.1(K) R63.2 U13.1(VOUT)
D5V_OUT2: C163.1 D2.1(K) R120.2 U23.1(VOUT)
D5V_VREG: C371.1 R317.2 R321.1 U51.17(VREG5)
D12V: C156.1 C158.1 C171.1 C188.1 C193.1 C201.1 C339.1 C340.1 C341.1 C342.1 C343.1 C344.1 C345.1 C346.1 C347.1 C348.1 C349.1 C350.1 JT1.a1(D-c1) JT1.a2(D-c2) JT1.a3(D-c3) JT1.b1(D-d1) JT1.b2(D-d2) JT1.b3(D-d3) U25.2(VIN1) U25.11(VIN2) U51.2(VIN1) U51.11(VIN2) U52.2(VIN1) U52.11(VIN2) ; also on sheet 17
GND: C9.2 C10.2 C22.2 C23.2 C24.2 C25.2 C26.2 C27.2 C28.1 C58.2 C59.1 C80.2 C95.2 C106.2 C111.1 C114.2 C118.2 C123.2 C131.2 C140.2 C141.2 C143.2 C144.1 C145.2 C146.1 C155.2 C156.2 C157.2 C158.2 C163.2 C171.2 C177.2 C183.2 C188.2 C192.2 C193.2 C200.2 C201.2 C204.2 C205.2 C212.2 C213.2 C214.2 C221.2 C222.1 C224.2 C225.2 C228.1 C230.2 C237.2 C253.2 C265.2 C281.1 C283.2 C284.1 C286.2 C287.2 C288.2 C289.2 C303.2 C312.2 C313.2 C314.2 C315.2 C316.2 C317.2 C318.2 C319.2 C320.2 C321.2 C339.2 C340.2 C341.2 C342.2 C343.2 C344.2 C345.2 C346.2 C347.2 C348.2 C349.2 C350.2 C370.2 C371.2 C373.2 C374.2 C402.1 C403.1 C404.1 C405.1 C406.1 C407.1 C408.1 C409.1 C411.1 C412.1 C413.1 C414.1 C415.1 C510.1 C511.1 C536.1 C537.1 C538.1 C539.1 C540.1 C541.1 C586.1 C587.1 C588.1 C589.1 C590.1 C609.2 C610.2 C611.2 C612.2 C613.2 J4.2(6) J4.10 J6.2(DAT2_S) J6.5(DAT1_S) J6.8(DAT0_S) J6.11(CLK_S) J6.17(DDC/CEC_GND) J8.2(DAT2_S) J8.5(DAT1_S) J8.8(DAT0_S) J8.11(CLK_S) J8.17(DDC/CEC_GND) J11.6 JT1.ab1(G-cd1) JT1.ab2(G-cd2) JT1.ab3(G-cd3) JT1.ab4(G-cd4) JT1.ab5(G-cd5) JT1.ab6(G-cd6) JT1.ab7(G-cd7) JT1.ab8(G-cd8) JT1.ab9(G-cd9) JT1.ab10(G-cd10) JT1.cd1(G-cd5) JT1.cd2(G-cd4) JT1.cd3(G-cd3) JT1.cd4(G-cd2) JT1.cd5(G-cd1) JT1.cd6(G-cd6) JT1.cd7(G-cd7) JT1.cd8(G-cd8) JT1.cd9(G-cd9) JT1.cd10(G-cd10) P1.AC17(IO_2A_0_AC17/DEV_CLRN/LVDS2A_24P/DQ31) P1.AC19(VREFB2AN0_2A) P1.AF18(IO_2A_2_AF18/DEV_OE/LVDS2A_23P/DQ31) P1.AJ16(IO_2A_12_AJ16/PR_REQUEST/LVDS2A_18P/DQ29) P1.K17(VREFB2LN0_2L) Q3.2(S) Q4.2(S) R14.1 R40.2 R56.2 R58.1 R60.1 R65.1 R67.2 R68.2 R70.2 R76.2 R78.1 R90.2 R91.2 R95.2 R114.2 R116.1 R117.1 R122.1 R124.2 R125.2 R127.2 R135.1 R138.1 R147.1 R159.2 R160.2 R163.2 R178.2 R221.1 R237.2 R238.1 R245.1 R247.1 R254.2 R259.2 R308.1 R309.1 R310.1 R311.1 R382.2 R383.2 R389.2 R392.2 R409.1 R412.2 R414.2 R417.1 R418.2 R421.2 R439.2 R440.2 R450.2 R454.2 R460.2 U5.4(PGND) U5.8(GND) U5.11(TPAD) U6.B3(VSS) U13.2(GND) U14.4(PGND) U14.8(GND) U14.11(TPAD) U15.3(GND1) U15.8(GND2) U17.3(GND1) U17.8(GND2) U19.7(GND1) U19.19(GND2) U19.30(GND3) U19.41(GND4) U19.49(PAD) U20.3(GND1) U20.8(GND2) U21.1(GND) U23.2(GND) U24.3(GND1) U24.8(GND2) U25.3(PGND1) U25.4(PGND2) U25.5(PGND3) U25.8(PGND4) U25.9(PGND5) U25.10(PGND6) U25.12(AGND) U27.3(GND1) U27.8(GND2) U29.7(GND1) U29.19(GND2) U29.30(GND3) U29.41(GND4) U29.49(PAD) U30.3(GND1) U30.8(GND2) U31.1(GND) U34.4(PGND) U34.8(GND) U34.11(TPAD) U38.4(GND) U43.8(VSSA) U43.23(VSS) U43.47(VSSS) U45.2(GND) U51.3(PGND1) U51.4(PGND2) U51.5(PGND3) U51.8(PGND4) U51.9(PGND5) U51.10(PGND6) U51.12(AGND) U52.3(PGND1) U52.4(PGND2) U52.5(PGND3) U52.8(PGND4) U52.9(PGND5) U52.10(PGND6) U52.12(AGND) Y5.2(GND) Y5.4(GND) ; also on sheet 1 2 3 4 5 14 15 16 17
VCC_D0V9: R422.2 ; also on sheet 16 17
VCC_DDR3: C23.1 C24.1 C114.1 C118.1 C224.1 C225.1 R38.1 R64.1 R195.1 U5.2(VLDOIN) U14.2(VLDOIN) U34.2(VLDOIN) ; also on sheet 4 14 15 16 17
VCC_IO3V0: R77.1 R96.1 R105.1 R137.1 R164.1 R172.1 U21.2(VREF1) U31.2(VREF1) ; also on sheet 1 2 3
VCCIO_D1V8: J4.4(7) R15.1 R41.2 R43.1 R398.2 R400.2 R401.2 R406.1 R408.1 R410.2 R413.2 R416.1 R420.2 U6.B4(VCC) ; also on sheet 16 17
VCCIO_EN: R237.1 U43.30(PA9) ; also on sheet 17
5338_SCL1: R249.1 U43.35(PF6) ; also on sheet 5
5338_SCL2: R255.1 U43.45(PB8) ; also on sheet 5
5338_SDA1: R250.1 U43.36(PF7) ; also on sheet 5
5338_SDA2: R256.1 U43.46(PB9) ; also on sheet 5
A1_1: R383.1 R384.2 U19.27(TEST/A1)
A1_2: R440.1 R441.2 U29.27(TEST/A1)
A_SPI_CLK: R216.1 U38.6(DCLK) U43.15(PA5)
A_SPI_CS: R224.1 U38.1(nCS) U43.14(PA4)
A_SPI_DI: U38.5(ASDI) U43.17(PA7)
A_SPI_DO: U38.2(DATA) U43.16(PA6)
AD1: P1.AH17(IO_2A_19_AH17/PLL_2A_CLKOUT0N/DATA26/LVDS2A_15N/DQ28) R408.2 R409.2
AD2: P1.AG17(IO_2A_18_AG17/PLL_2A_CLKOUT0P,PLL_2A_CLKOUT0,PLL_2A_FB0/DATA27/LVDS2A_15P/DQ28) R416.2 R417.2
ARM_GPIO0: R696.2 U43.40(PB4)
ARM_GPIO1: R698.2 U43.41(PB5)
ARM_GPIO2: R697.2 U43.42(PB6)
ARM_nRST: C611.1 J11.1 R474.2 U43.7(NRST)
ARM_PWS0: R708.1 U43.20(PB2)
ARM_PWS1: R709.1 U43.19(PB1)
ARM_PWS2: R710.1 U43.18(PB0)
ARM_SPI_CLK: R693.2 U43.26(PB13)
ARM_SPI_DI: R694.2 U43.28(PB15)
ARM_SPI_DO: R695.2 U43.27(PB14)
ARM_SPI_NSS: R691.2 U43.25(PB12)
AS_DATA0: P1.AJ11(AS_DATA0,ASDO) R703.2
AS_DATA1: P1.AK12(AS_DATA1) R704.2
AS_DATA2: P1.AK11(AS_DATA2) R705.2
AS_DATA3: P1.AF15(AS_DATA3) R706.2
CLKUSR: P1.AK16(IO_2A_13_AK16/CLKUSR/LVDS2A_18N/DQ29) ; also on sheet 5
CONF_DONE: P1.AM12(CONF_DONE) R401.1
CONN_TX+0: JT1.c3(D-c3) ; also on sheet 5
CONN_TX+1: JT1.c4(D-c4) ; also on sheet 5
CONN_TX+2: JT1.c5(D-c5) ; also on sheet 5
CONN_TX+3: JT1.c6(D-c6) ; also on sheet 5
CONN_TX+4: JT1.c7(D-c7) ; also on sheet 5
CONN_TX+5: JT1.c8(D-c8) ; also on sheet 5
CONN_TX+6: JT1.c9(D-c9) ; also on sheet 5
CONN_TX+7: JT1.c10(D-c10) ; also on sheet 5
CONN_TX-0: JT1.d3(D-d3) ; also on sheet 5
CONN_TX-1: JT1.d4(D-d4) ; also on sheet 5
CONN_TX-2: JT1.d5(D-d5) ; also on sheet 5
CONN_TX-3: JT1.d6(D-d6) ; also on sheet 5
CONN_TX-4: JT1.d7(D-d7) ; also on sheet 5
CONN_TX-5: JT1.d8(D-d8) ; also on sheet 5
CONN_TX-6: JT1.d9(D-d9) ; also on sheet 5
CONN_TX-7: JT1.d10(D-d10) ; also on sheet 5
DCLK: P1.AJ10(DCLK) R42.1
DCLK1: R41.1 R42.2 U6.B2(C)
EQ_SEL/A0_1: R66.2 R67.1 U19.21(EQ_SEL/A0)
EQ_SEL/A0_2: R123.2 R124.1 U29.21(EQ_SEL/A0)
F_ARM_GPIO0: P1.E19(IO_2L_31_E19/DQ2) R696.1
F_ARM_GPIO1: P1.D19(IO_2L_47_D19/DQ0) R698.1
F_ARM_GPIO2: P1.F19(IO_2L_30_F19/DQ2) R697.1
F_ARM_SPI_CLK: P1.F18(IO_2L_20_F18/DQS4) R693.1
F_ARM_SPI_DI: P1.H19(IO_2L_23_H19/CLK_2L_0N/DQ4) R694.1
F_ARM_SPI_DO: P1.E18(IO_2L_25_E18/CLK_2L_1N/DQ3) R695.1
F_ARM_SPI_NSS: P1.G18(IO_2L_18_G18/PLL_2L_CLKOUT0P,PLL_2L_CLKOUT0,PLL_2L_FB0/DQ4) R691.1
F_HM21_SCL: P1.L18(IO_2L_3_L18/DQ7) R187.1
F_HM21_SDA: P1.K18(IO_2L_2_K18/DQ7) R186.1
F_HM_TX_SCL1: P1.B21(IO_2L_44_B21/DQS0) R183.1
F_HM_TX_SCL2: P1.D20(IO_2L_35_D20/DQ2) R185.1
F_HM_TX_SCL3: P1.F20(IO_2L_27_F20/DQ3) R180.1
F_HM_TX_SCL4: P1.L20(IO_2L_10_L20/DQ6) R189.1
F_HM_TX_SCL21: P1.M18(IO_2L_1_M18/DQ7) R190.1
F_HM_TX_SDA1: P1.A21(IO_2L_43_A21/DQ0) R182.1
F_HM_TX_SDA2: P1.C20(IO_2L_34_C20/DQ2) R184.1
F_HM_TX_SDA3: P1.G20(IO_2L_26_G20/RZQ_2L/DQ3) R179.1
F_HM_TX_SDA4: P1.L19(IO_2L_9_L19/DQSN6) R188.1
F_HM_TX_SDA21: P1.M17(IO_2L_0_M17/DQ7) R191.1
F_nCS0: P1.AN10(NCSO0) R707.1
F_RX_5V_N: P1.K21(IO_2L_6_K21/DQ6) R192.1
F_RX_HPD_N: P1.L21(IO_2L_5_L21/DQSN7) R181.1
FCLT_GPIO0: P1.E17(IO_2L_24_E17/CLK_2L_1P/DQ3) R711.1
FCLT_GPIO1: P1.H18(IO_2L_19_H18/PLL_2L_CLKOUT0N/DQ4) R712.1
FCLT_GPIO2: P1.G21(IO_2L_16_G21/DQS5) R713.1
FCLT_GPIO3: P1.G17(IO_2L_21_G17/DQSN4) R714.1
FCLT_GPIO4: P1.H17(IO_2L_15_H17/DQ5) R51.1
FCLT_GPIO5: P1.J17(IO_2L_14_J17/DQ5) R47.1
FCLT_GPIO6: P1.D22(IO_2L_32_D22/DQS2) R54.1
FCLT_GPIO7: P1.M21(IO_2L_4_M21/DQS7) R53.1
HD_SCL1: R98.2 R104.1 R107.2 U21.6(SCL2)
HD_SCL2: R165.2 R171.1 R173.2 U31.6(SCL2)
HD_SDA1: R99.2 R100.1 R108.2 U21.5(SDA2)
HD_SDA2: R166.2 R167.1 R174.2 U31.5(SDA2)
HDMI_1_TCX+: J6.10(CLK+) R82.2 U17.4(IO3) U17.7(NC3) U19.26(OUT_CLKP)
HDMI_1_TCX-: J6.12(CLK-) R80.2 U17.5(IO4) U17.6(NC4) U19.25(OUT_CLKN)
HDMI_1_TX0+: J6.7(DAT0+) R84.2 U17.1(IO1) U17.10(NC1) U19.29(OUT_D0P)
HDMI_1_TX0-: J6.9(DAT0-) R83.2 U17.2(IO2) U17.9(NC2) U19.28(OUT_D0N)
HDMI_1_TX1+: J6.4(DAT1+) R86.2 U19.32(OUT_D1P) U20.4(IO3) U20.7(NC3)
HDMI_1_TX1-: J6.6(DAT1-) R85.2 U19.31(OUT_D1N) U20.5(IO4) U20.6(NC4)
HDMI_1_TX2+: J6.1(DAT2+) R88.2 U19.35(OUT_D2P) U20.1(IO1) U20.10(NC1)
HDMI_1_TX2-: J6.3(DAT2-) R87.2 U19.34(OUT_D2N) U20.2(IO2) U20.9(NC2)
HDMI_2_TCX+: J8.10(CLK+) R144.2 U27.4(IO3) U27.7(NC3) U29.26(OUT_CLKP)
HDMI_2_TCX-: J8.12(CLK-) R142.2 U27.5(IO4) U27.6(NC4) U29.25(OUT_CLKN)
HDMI_2_TX0+: J8.7(DAT0+) R149.2 U27.1(IO1) U27.10(NC1) U29.29(OUT_D0P)
HDMI_2_TX0-: J8.9(DAT0-) R146.2 U27.2(IO2) U27.9(NC2) U29.28(OUT_D0N)
HDMI_2_TX1+: J8.4(DAT1+) R153.2 U29.32(OUT_D1P) U30.4(IO3) U30.7(NC3)
HDMI_2_TX1-: J8.6(DAT1-) R150.2 U29.31(OUT_D1N) U30.5(IO4) U30.6(NC4)
HDMI_2_TX2+: J8.1(DAT2+) R158.2 U29.35(OUT_D2P) U30.1(IO1) U30.10(NC1)
HDMI_2_TX2-: J8.3(DAT2-) R155.2 U29.34(OUT_D2N) U30.2(IO2) U30.9(NC2)
HDMI_HPD_IN1: Q3.3(D) R77.2 R385.2 R386.2
HDMI_HPD_IN2: Q4.3(D) R137.2 R444.2 R446.2
HDMI_SCL_1: J6.15(SCL) R93.1 R101.1 R107.1 U15.1(IO1) U15.10(NC1)
HDMI_SCL_2: J8.15(SCL) R161.1 R169.1 R173.1 U24.1(IO1) U24.10(NC1)
HDMI_SDA_1: J6.16(SDA) R94.1 R102.1 R108.1 U15.2(IO2) U15.9(NC2)
HDMI_SDA_2: J8.16(SDA) R162.1 R170.1 R174.1 U24.2(IO2) U24.9(NC2)
HM21_SCL: R187.2 ; also on sheet 1
HM21_SDA: R186.2 ; also on sheet 1
HM_1_TCX+: C115.1 ; also on sheet 5
HM_1_TCX-: C113.1 ; also on sheet 5
HM_1_TX0+: C120.1 ; also on sheet 5
HM_1_TX0-: C117.1 ; also on sheet 5
HM_1_TX1+: C130.1 ; also on sheet 5
HM_1_TX1-: C122.1 ; also on sheet 5
HM_1_TX2+: C133.1 ; also on sheet 5
HM_1_TX2-: C132.1 ; also on sheet 5
HM_2_TCX+: C181.1 ; also on sheet 5
HM_2_TCX-: C178.1 ; also on sheet 5
HM_2_TX0+: C187.1 ; also on sheet 5
HM_2_TX0-: C185.1 ; also on sheet 5
HM_2_TX1+: C194.1 ; also on sheet 5
HM_2_TX1-: C191.1 ; also on sheet 5
HM_2_TX2+: C202.1 ; also on sheet 5
HM_2_TX2-: C199.1 ; also on sheet 5
HM_SCL_1: J5.2 P1.C19(IO_2L_46_C19/DQ0) R75.2
HM_SCL_2: J7.2 P1.A20(IO_2L_41_A20/DQSN1) R132.2
HM_SCL_3: P1.D21(IO_2L_29_D21/PLL_2L_CLKOUT1N/DQSN3) ; also on sheet 3
HM_SCL_4: P1.J20(IO_2L_12_J20/DQ5) ; also on sheet 2
HM_SDA_1: J5.1 P1.B20(IO_2L_45_B20/DQSN0) R73.2
HM_SDA_2: J7.1 P1.A19(IO_2L_40_A19/DQS1) R130.2
HM_SDA_3: P1.E21(IO_2L_28_E21/PLL_2L_CLKOUT1P,PLL_2L_CLKOUT1,PLL_2L_FB1/DQS3) ; also on sheet 3
HM_SDA_4: P1.M20(IO_2L_11_M20/DQ6) ; also on sheet 2
HM_TX_HPD1: P1.B22(IO_2L_42_B22/DQ0) R386.1 R387.1
HM_TX_HPD2: P1.C22(IO_2L_33_C22/DQSN2) R446.1 R447.1
HM_TX_HPD3: P1.H20(IO_2L_13_H20/DQ5) ; also on sheet 3
HM_TX_HPD4: P1.K19(IO_2L_8_K19/DQS6) ; also on sheet 2
HM_TX_SCL1: R105.2 R183.2 U21.3(SCL1)
HM_TX_SCL2: R172.2 R185.2 U31.3(SCL1)
HM_TX_SCL3: R180.2 ; also on sheet 3
HM_TX_SCL4: R189.2 ; also on sheet 2
HM_TX_SCL21: R190.2 ; also on sheet 1
HM_TX_SDA1: R96.2 R182.2 U21.4(SDA1)
HM_TX_SDA2: R164.2 R184.2 U31.4(SDA1)
HM_TX_SDA3: R179.2 ; also on sheet 3
HM_TX_SDA4: R188.2 ; also on sheet 2
HM_TX_SDA21: R191.2 ; also on sheet 1
HPD_IN1: J6.19(HPLG) Q3.1(G) R78.2 R388.2 U15.5(IO4) U15.6(NC4)
HPD_IN2: J8.19(HPLG) Q4.1(G) R138.2 R448.2 U24.5(IO4) U24.6(NC4)
HPD_SNK_1: R385.1 R388.1 U19.33(HPD_SNK)
HPD_SNK_2: R444.1 R448.1 U29.33(HPD_SNK)
HPD_SRC_1: R387.2 U19.4(HPD_SRC)
HPD_SRC_2: R447.2 U29.4(HPD_SRC)
I2C_EN/PIN_1: R381.2 R382.1 U19.10(I2C_EN/PIN)
I2C_EN/PIN_2: R436.2 R439.1 U29.10(I2C_EN/PIN)
LED1: P1.A18(IO_2L_38_A18/DQ1) ; also on sheet 17
LED2: P1.B18(IO_2L_39_B18/DQ1) ; also on sheet 17
LED3: P1.D17(IO_2L_37_D17/DQ1) ; also on sheet 17
LED4: P1.C18(IO_2L_36_C18/DQ1) ; also on sheet 17
LED_HDMI21: P1.F21(IO_2L_17_F21/DQSN5) ; also on sheet 17
M_AS_DATA0: R703.1 U6.D3(DQ0)
M_AS_DATA1: R704.1 U6.D2(DQ1)
M_AS_DATA2: R705.1 U6.C4(W#/DQ2)
M_AS_DATA3: R706.1 U6.D4(HOLD#/DQ3)
MSEL0: P1.AG15(MSEL0) R410.1 R412.1
MSEL1: P1.AG13(MSEL1) R413.1
MSEL2: P1.AG12(MSEL2) R414.1
nCE: P1.AF14(NCE) R418.1
nCONFIG: P1.AF13(NCONFIG) R420.1
nCS0: R43.2 R707.2 U6.C2(S#)
nIO_PULLUP: P1.AE14(NIO_PULLUP) R421.1 R422.1
nSTATUS: P1.AM11(NSTATUS) R398.1
PRE_SEL_1: R68.1 R69.2 U19.20(PRE_SEL)
PRE_SEL_2: R125.1 R126.2 U29.20(PRE_SEL)
RX_5V_N: R192.2 ; also on sheet 1
RX_HPD_N: R181.2 ; also on sheet 1
SCL_CTL_1: R74.2 R75.1 U19.15(SCL_CTL)
SCL_CTL_2: R131.2 R132.1 U29.15(SCL_CTL)
SCL_SNK_1: R93.2 U19.38(SCL_SNK)
SCL_SNK_2: R161.2 U29.38(SCL_SNK)
SCL_SRC_1: R90.1 R98.1 U19.46(SCL_SRC)
SCL_SRC_2: R159.1 R165.1 U29.46(SCL_SRC)
SDA_CTL_1: R72.2 R73.1 U19.16(SDA_CTL)
SDA_CTL_2: R129.2 R130.1 U29.16(SDA_CTL)
SDA_SNK_1: R94.2 U19.39(SDA_SNK)
SDA_SNK_2: R162.2 U29.39(SDA_SNK)
SDA_SRC_1: R91.1 R99.1 U19.47(SDA_SRC)
SDA_SRC_2: R160.1 R166.1 U29.47(SDA_SRC)
SIG_EN_1: R70.1 R71.2 U19.17(SIG_EN)
SIG_EN_2: R127.1 R128.2 U29.17(SIG_EN)
SWAP/POL_1: R389.1 R391.2 U19.1(SWAP/POL)
SWAP/POL_2: R450.1 R452.2 U29.1(SWAP/POL)
SWCLK: J11.2 R221.2 U43.37(PA14)
SWDIO: J11.4 R225.2 U43.34(PA13)
TCK: P1.AH12(TCK) R699.1
TDI: P1.AH13(TDI) R702.1
TDO: P1.AJ12(TDO) R700.1
TMS: P1.AL10(TMS) R701.1
TRST: P1.AL11(TRST) R400.1
TX_TERM_1: R392.1 R393.2 U19.36(TX_TERM_CTL)
TX_TERM_2: R454.1 R455.2 U29.36(TX_TERM_CTL)
UART_RXD: J11.3 U43.13(PA3)
UART_TXD: J11.5 U43.12(PA2)
VREF_DDR3_A: C9.1 C10.1 U5.6(REFOUT) ; also on sheet 4
VREF_DDR3_B: C58.1 C80.1 U14.6(REFOUT) ; also on sheet 15
VREF_DDR3_C: C237.1 C253.1 U34.6(REFOUT) ; also on sheet 14
VTT_DDR3_A: C25.1 C26.1 C27.1 U5.3(VO) U5.5(VOSNS) ; also on sheet 4
VTT_DDR3_B: C123.1 C131.1 C140.1 U14.3(VO) U14.5(VOSNS) ; also on sheet 15
VTT_DDR3_C: C205.1 C213.1 C221.1 U34.3(VO) U34.5(VOSNS) ; also on sheet 14
XTL25N: C281.2 U43.6(PF1/OSC_OUT) Y5.1(XTALI)
XTL25P: C284.2 U43.5(PF0/OSC_IN) Y5.3(XTALO)
N22024981: R22.1 U5.9(PGOOD)
N22025053: C111.2 R64.2 R76.1 U14.1(REFIN)
N22025271: R61.1 U14.9(PGOOD)
N22025327: C228.2 R178.1 R195.2 U34.1(REFIN)
N22025525: R198.1 U34.9(PGOOD)
N22025799: R19.1 U5.7(EN)
N22025867: R62.1 U14.7(EN)
N22025914: R197.1 U34.7(EN)
N22026405: R259.1 R272.1 U45.5(FB)
N22026409: L7.1 U45.3(SW)
N22026570: C28.2 R38.2 R40.1 U5.1(REFIN)
N22071827: J4.9(5) R406.2 R702.2
N22071832: J4.5(3) R15.2 R701.2
N22072215: J4.1 R14.2 R699.2
N22072232: J4.3(2) R700.2
N22086073: JT1.a10(D-c10) R54.2
N22086076: JT1.b9(D-d9) R47.2
N22086079: JT1.a9(D-c9) R51.2
N22086210: JT1.b10(D-d10) R53.2
N22318019: C130.2 U19.5(IN_D1P)
N22318021: C122.2 U19.6(IN_D1N)
N22318023: C133.2 U19.2(IN_D2P)
N22318025: C132.2 U19.3(IN_D2N)
N22318199: C143.1 J6.MTG1 J6.MTG2 J6.MTG3 J6.MTG4 R58.2
N22318292: C144.2 R110.1 U21.7(VREF2) U21.8(EN)
N22318294: C120.2 U19.8(IN_D0P)
N22318980: C117.2 U19.9(IN_D0N)
N22318988: C115.2 U19.11(IN_CLKP)
N22318990: C113.2 U19.12(IN_CLKN)
N22319096: R65.2 U19.22(VSADJ)
N22319158: R95.1 U19.45(SPDIF_IN)
N22319174: C141.1 U19.42(OE)
N22319555: J6.18(+5V) R63.1
N22319599: R60.2 U13.3(OCB)
N22319611: R56.1 R57.1 U13.4(EN)
N22336290: C194.2 U29.5(IN_D1P)
N22336292: C191.2 U29.6(IN_D1N)
N22336294: C202.2 U29.2(IN_D2P)
N22336296: C199.2 U29.3(IN_D2N)
N22336470: C214.1 J8.MTG1 J8.MTG2 J8.MTG3 J8.MTG4 R116.2
N22336560: C222.2 R175.1 U31.7(VREF2) U31.8(EN)
N22336562: C187.2 U29.8(IN_D0P)
N22337251: C185.2 U29.9(IN_D0N)
N22337253: C181.2 U29.11(IN_CLKP)
N22337255: C178.2 U29.12(IN_CLKN)
N22337367: R122.2 U29.22(VSADJ)
N22337429: R163.1 U29.45(SPDIF_IN)
N22337445: C212.1 U29.42(OE)
N22337826: J8.18(+5V) R120.1
N22337863: R117.2 U23.3(OCB)
N22337874: R114.1 R115.1 U23.4(EN)
N22432680: P1.A13(VREFP_ADC) P1.B13(VREFN_ADC) R460.1
N22451830: R135.2 R136.1 U25.18(MODE)
N22451844: C164.1 U25.1(BOOT)
N22451846: C164.2 L4.1 U25.6(SW1) U25.7(SW2)
N22451862: C190.2 R147.2 R151.1 U25.13(FB)
N22451950: C183.1 U25.14(SS)
N22452196: R140.2 U25.16(PGOOD)
N22462383: R260.2 U45.1(EN/PG)
N22647853: R309.2 R317.1 U51.18(MODE)
N22647875: C372.1 U51.1(BOOT)
N22647877: C372.2 L12.1 U51.6(SW1) U51.7(SW2)
N22647893: C382.2 R304.1 R308.2 U51.13(FB)
N22647973: C370.1 U51.14(SS)
N22648227: R321.2 U51.16(PGOOD)
N22660428: R254.1 U43.44(BOOT0)
N22766072: R311.2 R318.1 U52.18(MODE)
N22766094: C375.1 U52.1(BOOT)
N22766096: C375.2 L13.1 U52.6(SW1) U52.7(SW2)
N22766112: C383.2 R305.1 R310.2 U52.13(FB)
N22766192: C373.1 U52.14(SS)
N22766425: R322.2 U52.16(PGOOD)
N22862307: JT1.d1(D-d1) R709.2
N22862309: JT1.c1(D-c1) R708.2
N22862311: JT1.c2(D-c2) R710.2
N22881224: JT1.a8(D-c8) R713.2
N22881226: JT1.b7(D-d7) R712.2
N22881228: JT1.a7(D-c7) R711.2
N22881230: JT1.b8(D-d8) R714.2

Not connected (* = marked no-connect by the designer): J4 6(8) 7(4) 8(9); J6 13(CEC) 14(NC)*; J8 13(CEC) 14(NC)*; J11 7; JT1 a4(D-c4) a5(D-c5) a6(D-c6) b4(D-d4) b5(D-d5) b6(D-d6) d2(D-d2); P1 AD17(IO_2A_1_AD17/CRC_ERROR/LVDS2A_24N/DQ31) AD19(IO_2A_6_AD19/LVDS2A_21P/DQ30) AE16(IO_2A_10_AE16/NPERSTL0/LVDS2A_19P/DQ30) AE17(IO_2A_11_AE17/PR_READY/LVDS2A_19N/DQ30) AE18(IO_2A_7_AE18/PR_ERROR/LVDS2A_21N/DQ30) AE19(IO_2A_5_AE19/CVP_CONFDONE/LVDS2A_22N/DQSN31) AF16(IO_2A_9_AF16/PR_DONE/LVDS2A_20N/DQSN30) AF19(IO_2A_4_AF19/LVDS2A_22P/DQS31) AG16(IO_2A_8_AG16/NPERSTL1/LVDS2A_20P/DQS30) AG18(IO_2A_3_AG18/INIT_DONE/LVDS2A_23N/DQ31) AH14(IO_2A_21_AH14/DATA24/LVDS2A_14N/DQSN28) AH15(IO_2A_15_AH15/DATA30/LVDS2A_17N/DQ29) AH18(IO_2A_22_AH18/CLK_2A_0P/DATA23/LVDS2A_13P/DQ28) AH19(IO_2A_23_AH19/CLK_2A_0N/DATA22/LVDS2A_13N/DQ28) AJ14(IO_2A_20_AJ14/DATA25/LVDS2A_14P/DQS28) AJ15(IO_2A_14_AJ15/DATA31/LVDS2A_17P/DQ29) AJ17(IO_2A_16_AJ17/DATA29/LVDS2A_16P/DQS29) AK13(IO_2A_47_AK13/DATA0/LVDS2A_1N/DQ24) AK14(IO_2A_31_AK14/DATA16/LVDS2A_9N/DQ26) AK17(IO_2A_17_AK17/DATA28/LVDS2A_16N/DQSN29) AK18(IO_2A_26_AK18/RZQ_2A/LVDS2A_11P/DQ27) AL13(IO_2A_46_AL13/DATA1/LVDS2A_1P/DQ24) AL14(IO_2A_30_AL14/DATA17/LVDS2A_9P/DQ26) AL15(IO_2A_25_AL15/CLK_2A_1N/DATA20/LVDS2A_12N/DQ27) AL16(IO_2A_28_AL16/PLL_2A_CLKOUT1P,PLL_2A_CLKOUT1,PLL_2A_FB1/DATA19/LVDS2A_10P/DQS27) AL18(IO_2A_27_AL18/NCEO/LVDS2A_11N/DQ27) AM10(NCSO1) AM13(IO_2A_41_AM13/DATA6/LVDS2A_4N/DQSN25) AM15(IO_2A_24_AM15/CLK_2A_1P/DATA21/LVDS2A_12P/DQ27) AM16(IO_2A_29_AM16/PLL_2A_CLKOUT1N/DATA18/LVDS2A_10N/DQSN27) AM17(IO_2A_32_AM17/DATA15/LVDS2A_8P/DQS26) AM18(IO_2A_34_AM18/DATA13/LVDS2A_7P/DQ26) AN12(IO_2A_38_AN12/DATA9/LVDS2A_5P/DQ25) AN13(IO_2A_40_AN13/DATA7/LVDS2A_4P/DQS25) AN14(IO_2A_36_AN14/DATA11/LVDS2A_6P/DQ25) AN15(IO_2A_42_AN15/DATA5/LVDS2A_3P/DQ24) AN17(IO_2A_33_AN17/DATA14/LVDS2A_8N/DQSN26) AN18(IO_2A_35_AN18/DATA12/LVDS2A_7N/DQ26) AP10(NCSO2) AP12(IO_2A_39_AP12/DATA8/LVDS2A_5N/DQ25) AP14(IO_2A_37_AP14/DATA10/LVDS2A_6N/DQ25) AP15(IO_2A_43_AP15/DATA4/LVDS2A_3N/DQ24) AP16(IO_2A_44_AP16/DATA3/LVDS2A_2P/DQS24) AP17(IO_2A_45_AP17/DATA2/LVDS2A_2N/DQSN24) J19(IO_2L_22_J19/CLK_2L_0P/DQ4) J21(IO_2L_7_J21/DQ6); U6 A2(NC1)* A3(NC2)* A4(NC3/RESET#) A5(NC4)* B1(NC5)* B5(NC6)* C1(NC7)* C3(NC8)* C5(NC9)* D1(NC10)* D5(NC11)* E1(NC12)* E2(NC13)* E3(NC14)* E4(NC15)* E5(NC16)*; U15 4(IO3) 7(NC3); U19 18(NC1) 40(NC2) 44(ARC_OUT)*; U24 4(IO3) 7(NC3); U25 15(EN); U29 18(NC1) 40(NC2) 44(ARC_OUT)*; U43 2(PC13) 3(PC14/OSC32_IN) 4(PC15/OCS32_OUT) 10(PA0) 11(PA1) 21(PB10) 22(PB11) 33(PA12) 38(PA15) 39(PB3) 43(PB7); U51 15(EN); U52 15(EN)

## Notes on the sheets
sheet 6
- HDMI OUT2
- 差分信号的输入端是否加电容
  输出端是否加电感
- 电源去耦电容
- TMDS181配置管脚
- 5V输出限流
- 5V电源输出限流+防倒灌，limit（A）=6800/Rocb
- TMDS181芯片配置：I2C控制模式
- DDC输出选择
- HPD接入选择
- HPD信号经过TMDS181芯片转接，R392上件，R393 NC
  HPD信号直接由FPGA控制，R393上件，R392 NC
- DDCI2C 可选择接入TMDS181的SRC_I2C（默认）
  或者 直接接到PCA9306DC1A的I2C输入接口。
- DDC IIC信号经过TMDS181芯片转接，
  R247、R387、R245、R243 NC，R248、R244、R249、R246上件
  DDC IIC信号不经过TMDS181芯片转接，
  R248、R244、R249、R246 NC，R247、R387、R245、R243 NC
sheet 7
- HDMI OUT1
- 差分信号的输入端是否加电容
  输出端是否加电感
- 电源去耦电容
- TMDS181配置管脚
- 5V输出限流
- 5V电源输出限流+防倒灌，limit（A）=6800/Rocb
- TMDS181芯片配置：I2C控制模式
- DDC输出选择
- HPD接入选择
- HPD信号经过TMDS181芯片转接，R392上件，R393 NC
  HPD信号直接由FPGA控制，R393上件，R392 NC
- DDCI2C 可选择接入TMDS181的SRC_I2C（默认）
  或者 直接接到PCA9306DC1A的I2C输入接口。
- DDC IIC信号经过TMDS181芯片转接，
  R247、R387、R245、R243 NC，R248、R244、R249、R246上件
  DDC IIC信号不经过TMDS181芯片转接，
  R248、R244、R249、R246 NC，R247、R387、R245、R243 NC
sheet 8
- Power-up Sequence
  D0V9_EN -> D1V0_EN -> D1V8_EN -> VCCIO_EN
sheet 9
- REV
- DATE
- PAGES
- DESCRIPTION
- 1.0
- 2021/07/03
- ALL
- 初稿
- PAGE
- DESCRIPTION
- PAGE
- DESCRIPTION
- 1
- Description
- 18
- 2
- Power Tree
- 19
- 3
- FPGA PWR
- 20
- 4
- PWR2
- 21
- 5
- STM32F030
- 22
- 6
- HDMI21 IN
- 23
- 7
- HDMI20 OUT1
- 24
- 8
- HDMI20 OUT2
- 25
- 9
- HDMI20 OUT3
- 26
- 10
- HDMI20 OUT4
- 27
- 11
- 10AX032-(GX)
- 28
- 12
- 10AX032-(2K&2J)
- 29
- 13
- 10AX032-(3A&3B)
- 30
- 14
- 10AX032-(3C&3D)
- 15
- 10AX032-(2A&2L)
- 16
- 10AX032-PWR&GND
- 17
- Connector
- 原理图封装使用的是10AX27封装，但实际贴片10AX032，并且对于HDMI21的应用，
  需使用速度等级至少为-2的芯片，此板FPGA选型为10AX032H3F34E2SG。
sheet 10
- 3.3V 8A
- 0.75V
- 0.75V
- VFB=0.6V
- 1.2V
- 0.75V
- 0.75V
- VFB=0.6V
- 1.8V 2A
- 0.75V
- 0.75V
- VFB=0.6V
- 5V 8A
- VFB=0.6V
sheet 11
- PWOER TREE
- 12V
- VDD of STM32F030
- ≤120mA
- VIN of TPS51200
- x3
- D12V
- TPS568215
- 3.3V
- D3V3
- VDD of TMDS181
- ≤250mA
- x4
- BUCK，8A
- VDD of DS125MB203
- ≤685mA
- x2
- VDD of Si5338A
- ≤60mA
- x2
- VCC of 10AX027F34
- ≤18.739A
- Core voltage power supply
- D12V
- 0.9V
- VCC_D0V9
- TPS53355
- VCCP of 10AX027F34
- ≤1.982A
- Periphery circuitry and transceiver fabric interface power supply
- BUCK，30A
- VCCERAM of 10AX027F34
- ≤1.245A
- Embedded memory power supply
- D12V
- 1.03V
- VCC_D1V0
- TPS568215
- VCCR_GXB of 10AX027F34
- ≤5.118A
- Receiver power supply
- BUCK，8A
- VCCT_GXB of 10AX027F34
- ≤1.310A
- Transmitter power supply
- VCCPT of 10AX027F34
- ≤0.262A
- Power supply for programmable power technology and I/O pre-driver
- VCCH_GXB of 10AX027F34
- ≤1.868A
- Transceiver output buffer power supply
- D12V
- 1.8V
- VCC_D1V8
- TPS568215
- VCCA_PLL of 10AX027F34
- ≤0.077A
- PLL analog voltage regulator power supply
- BUCK，8A
- VDDO of Si5338A
- ≤30mA
- x2
- GROUP1
  VCC   0.9V
  VCCP   0.9V
  VCCERAM   0.9V
  VCCR_GXB   1.03V
  VCCT_GXB   1.03V
- VLDOIN of TPS51200
- x3
- VDD of DDR3
- x9
- VDDQ of DDR3
- x9
- D12V
- 1.5V
- VCC_DDR3
- VCCIO2J of 10AX027F34
- ≤260mA
- I/O buffers power supply of BANK 2J
- TPS568215
- BUCK，8A
- VCCIO2K of 10AX027F34
- ≤260mA
- I/O buffers power supply of BANK 2K
- VCCIO3A of 10AX027F34
- ≤260mA
- I/O buffers power supply of BANK 3A
- VCCIO3B of 10AX027F34
- ≤260mA
- I/O buffers power supply of BANK 3B
- GROUP2
  VCCPT   1.8V
  VCCH_GXB   1.8V
  VCCA_PLL   1.8V
  VCCA_PGM   1.8V
  VCCIO   1.8V
- VCCIO3C of 10AX027F34
- ≤260mA
- I/O buffers power supply of BANK 3C
- VCCIO3D of 10AX027F34
- ≤260mA
- I/O buffers power supply of BANK 3D
- D12V
- 1.2V
- D1V2
- TPS54240
- BUCK，2.5A
- VDD of TMDS181
- ≤550mA
- x4
- GROUP3
  VCCIO   1.5V/3.0V
- D12V
- TPS568215
- 5V
- D5V
- D5V_OUT of HDMI
- BUCK，8A
- D5V
- 1.8V
- D1V8
- TLV62569
- VDDO of Si5338A
- ≤550mA
- x4
- BUCK，2A
- D3V3
- 3.0V
- VCCIO_D3V0
- TLV62569
- BUCK，2A
- VCCIO2L of 10AX027F34
- I/O buffers power supply of BANK 2L
- VCCIO2A of 10AX027F34
- I/O buffers power supply of BANK 2A
- D3V3
- 1.8V
- VCCIO_D1V8
- TLV62569
- VCCPGM of 10AX027F34
- ≤0.1A
- Configuration pins power supply
- BUCK，2A
- VCCBAT of 10AX027F34
- ≤0.1A
- Battery back-up power supply(For design security volatile key register)
